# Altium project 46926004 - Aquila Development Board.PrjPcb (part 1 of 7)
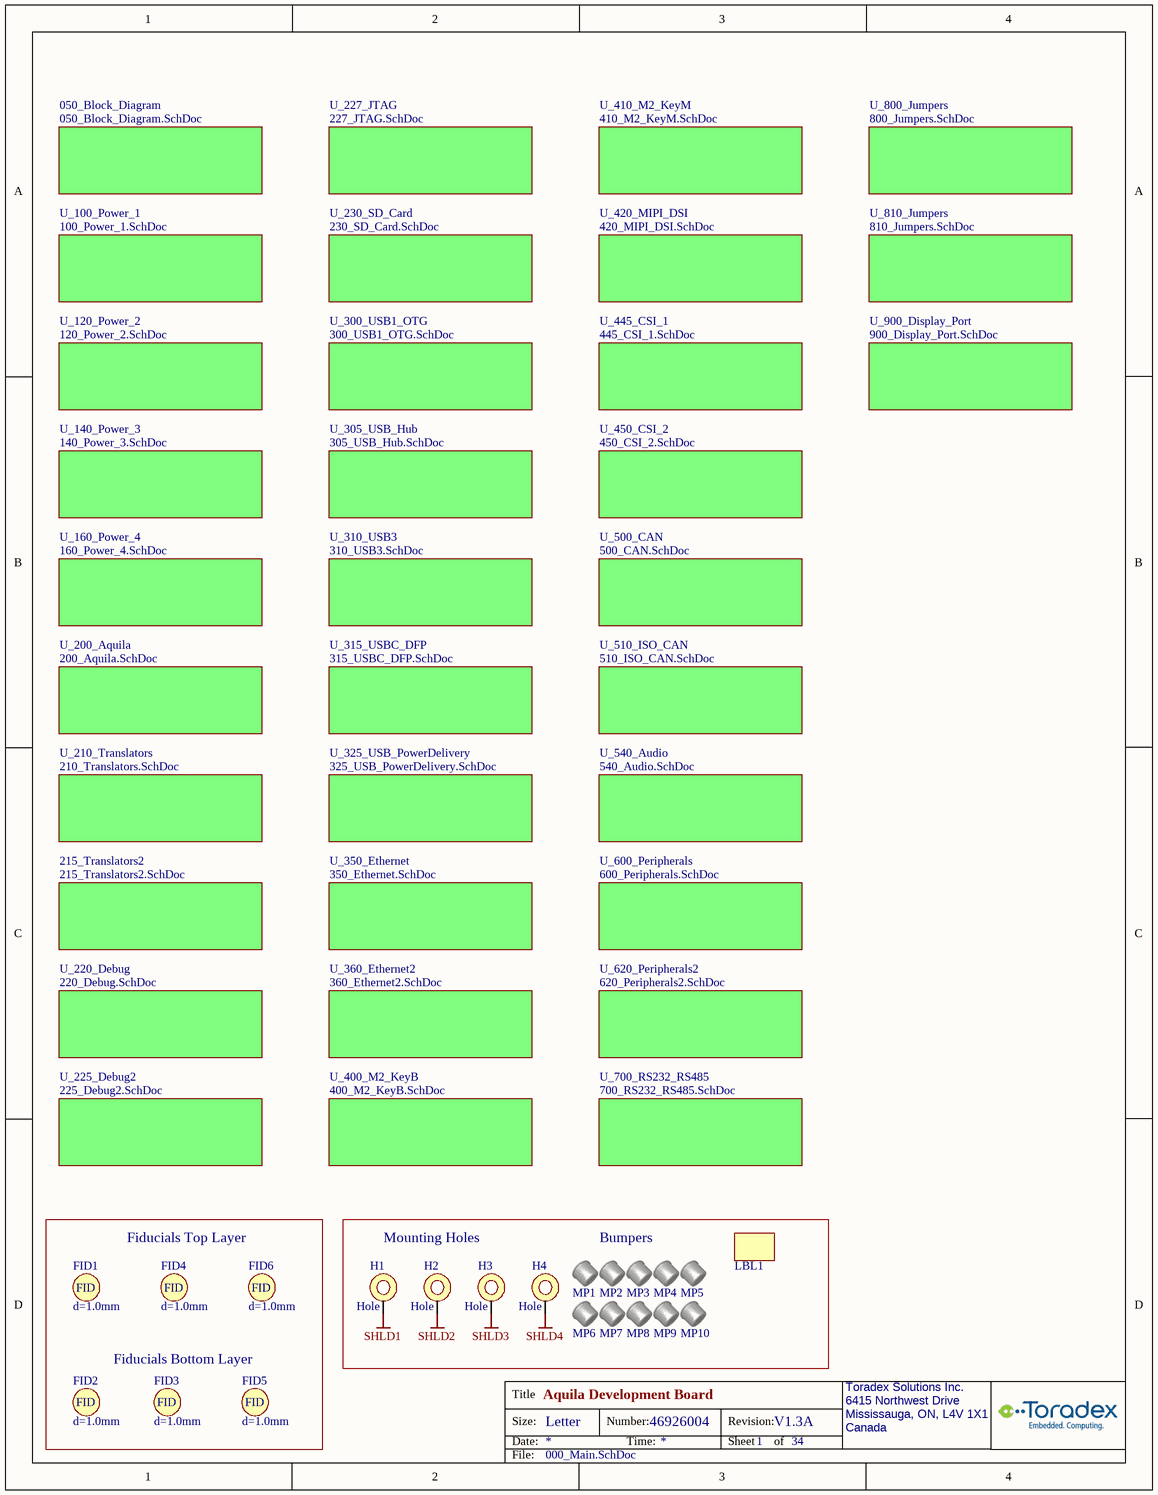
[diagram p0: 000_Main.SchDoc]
CompanyName: Toradex Solutions Inc.; DocumentNumber: 46926004; Revision: V1.3A; Title: Aquila Development Board
34 sheets, 1450 parts. Net scope: global (net labels, ports and power ports of the same name join across sheets).
Board file: 46926004.PcbDoc
Sheets:
  000_Main.SchDoc
    U_200_Aquila = 200_Aquila.SchDoc
    U_600_Peripherals = 600_Peripherals.SchDoc
    U_100_Power_1 = 100_Power_1.SchDoc
    U_210_Translators = 210_Translators.SchDoc
    U_220_Debug = 220_Debug.SchDoc
    U_300_USB1_OTG = 300_USB1_OTG.SchDoc
    U_310_USB3 = 310_USB3.SchDoc
    U_305_USB_Hub = 305_USB_Hub.SchDoc
    U_350_Ethernet = 350_Ethernet.SchDoc
    U_230_SD_Card = 230_SD_Card.SchDoc
    U_400_M2_KeyB = 400_M2_KeyB.SchDoc
    U_420_MIPI_DSI = 420_MIPI_DSI.SchDoc
    U_500_CAN = 500_CAN.SchDoc
    U_120_Power_2 = 120_Power_2.SchDoc
    U_140_Power_3 = 140_Power_3.SchDoc
    U_360_Ethernet2 = 360_Ethernet2.SchDoc
    U_410_M2_KeyM = 410_M2_KeyM.SchDoc
    U_540_Audio = 540_Audio.SchDoc
    U_620_Peripherals2 = 620_Peripherals2.SchDoc
    U_225_Debug2 = 225_Debug2.SchDoc
    U_227_JTAG = 227_JTAG.SchDoc
    215_Translators2 = 215_Translators2.SchDoc
    050_Block_Diagram = 050_Block_Diagram.SchDoc
    U_800_Jumpers = 800_Jumpers.SchDoc
    U_810_Jumpers = 810_Jumpers.SchDoc
    U_160_Power_4 = 160_Power_4.SchDoc
    U_510_ISO_CAN = 510_ISO_CAN.SchDoc
    U_325_USB_PowerDelivery = 325_USB_PowerDelivery.SchDoc
    U_700_RS232_RS485 = 700_RS232_RS485.SchDoc
    U_315_USBC_DFP = 315_USBC_DFP.SchDoc
    U_445_CSI_1 = 445_CSI_1.SchDoc
    U_450_CSI_2 = 450_CSI_2.SchDoc
    U_900_Display_Port = 900_Display_Port.SchDoc

## Sheet 000_Main.SchDoc: Aquila Development Board
size Letter portrait; Organization: Toradex Solutions Inc.; Address1: 6415 Northwest Drive; Address2: Mississauga, ON, L4V 1X1; Address3: Canada; SheetNumber: 1; SheetTotal: 34

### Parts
FID1  d=1.0mm  [FID_40X120_RND]  (no BOM)
FID2  d=1.0mm  [FID_40X120_RND]  (no BOM)
FID3  d=1.0mm  [FID_40X120_RND]  (no BOM)
FID4  d=1.0mm  [FID_40X120_RND]  (no BOM)
FID5  d=1.0mm  [FID_40X120_RND]  (no BOM)
FID6  d=1.0mm  [FID_40X120_RND]  (no BOM)
H1  Hole  [MTG_HOLE_0.125]  (no BOM)
H2  Hole  [MTG_HOLE_0.125]  (no BOM)
H3  Hole  [MTG_HOLE_0.125]  (no BOM)
H4  Hole  [MTG_HOLE_0.125]  (no BOM)
LBL1  SN Label 0.25x0.9 inch  [LABEL_0.25x0.9IN]  (value not drawn)  (no BOM)
MP1  SJ61A3  [3M-SJ61A3]  (value not drawn)
MP2  SJ61A3  [3M-SJ61A3]  (value not drawn)
MP3  SJ61A3  [3M-SJ61A3]  (value not drawn)
MP4  SJ61A3  [3M-SJ61A3]  (value not drawn)
MP5  SJ61A3  [3M-SJ61A3]  (value not drawn)
MP6  SJ61A3  [3M-SJ61A3]  (value not drawn)
MP7  SJ61A3  [3M-SJ61A3]  (value not drawn)
MP8  SJ61A3  [3M-SJ61A3]  (value not drawn)
MP9  SJ61A3  [3M-SJ61A3]  (value not drawn)
MP10  SJ61A3  [3M-SJ61A3]  (value not drawn)

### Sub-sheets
050_Block_Diagram = 050_Block_Diagram.SchDoc: no entries
215_Translators2 = 215_Translators2.SchDoc: no entries
U_100_Power_1 = 100_Power_1.SchDoc: no entries
U_120_Power_2 = 120_Power_2.SchDoc: no entries
U_140_Power_3 = 140_Power_3.SchDoc: no entries
U_160_Power_4 = 160_Power_4.SchDoc: no entries
U_200_Aquila = 200_Aquila.SchDoc: no entries
U_210_Translators = 210_Translators.SchDoc: no entries
U_220_Debug = 220_Debug.SchDoc: no entries
U_225_Debug2 = 225_Debug2.SchDoc: no entries
U_227_JTAG = 227_JTAG.SchDoc: no entries
U_230_SD_Card = 230_SD_Card.SchDoc: no entries
U_300_USB1_OTG = 300_USB1_OTG.SchDoc: no entries
U_305_USB_Hub = 305_USB_Hub.SchDoc: no entries
U_310_USB3 = 310_USB3.SchDoc: no entries
U_315_USBC_DFP = 315_USBC_DFP.SchDoc: no entries
U_325_USB_PowerDelivery = 325_USB_PowerDelivery.SchDoc: no entries
U_350_Ethernet = 350_Ethernet.SchDoc: no entries
U_360_Ethernet2 = 360_Ethernet2.SchDoc: no entries
U_400_M2_KeyB = 400_M2_KeyB.SchDoc: no entries
U_410_M2_KeyM = 410_M2_KeyM.SchDoc: no entries
U_420_MIPI_DSI = 420_MIPI_DSI.SchDoc: no entries
U_445_CSI_1 = 445_CSI_1.SchDoc: no entries
U_450_CSI_2 = 450_CSI_2.SchDoc: no entries
U_500_CAN = 500_CAN.SchDoc: no entries
U_510_ISO_CAN = 510_ISO_CAN.SchDoc: no entries
U_540_Audio = 540_Audio.SchDoc: no entries
U_600_Peripherals = 600_Peripherals.SchDoc: no entries
U_620_Peripherals2 = 620_Peripherals2.SchDoc: no entries
U_700_RS232_RS485 = 700_RS232_RS485.SchDoc: no entries
U_800_Jumpers = 800_Jumpers.SchDoc: no entries
U_810_Jumpers = 810_Jumpers.SchDoc: no entries
U_900_Display_Port = 900_Display_Port.SchDoc: no entries

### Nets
SHLD1: H1.0(MTG_HOLE)
SHLD2: H2.0(MTG_HOLE)
SHLD3: H3.0(MTG_HOLE)
SHLD4: H4.0(MTG_HOLE)

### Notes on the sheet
- Fiducials Top Layer
- Mounting Holes
- Bumpers
- Fiducials Bottom Layer

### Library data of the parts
FID1-FID6 = 0000-Fiducial-round: Fiducial round d=1.0mm
H1-H4 = 000-Hole-125mil
LBL1 = 000-Label-0.25x0.9IN: Label for Toradex serial number label 0.25x0.9 inch
MP1-MP10 = 1476-Bumper-10mmD-6mmH: (-40 to 85 DegC) Bumper Polyurethane, D: 9.5mm, H: 6.3mm, adhesive; Mfr: 3M; PN: 1476; Note: To be attached manually after SMT/TH assembly

## Sheet 200_Aquila.SchDoc: Aquila Development Board
size 566 x 398 mm; Organization: Toradex Solutions Inc.; Address1: 6415 Northwest Drive; Address2: Mississauga, ON, L4V 1X1; Address3: Canada; SheetNumber: 7; SheetTotal: 34
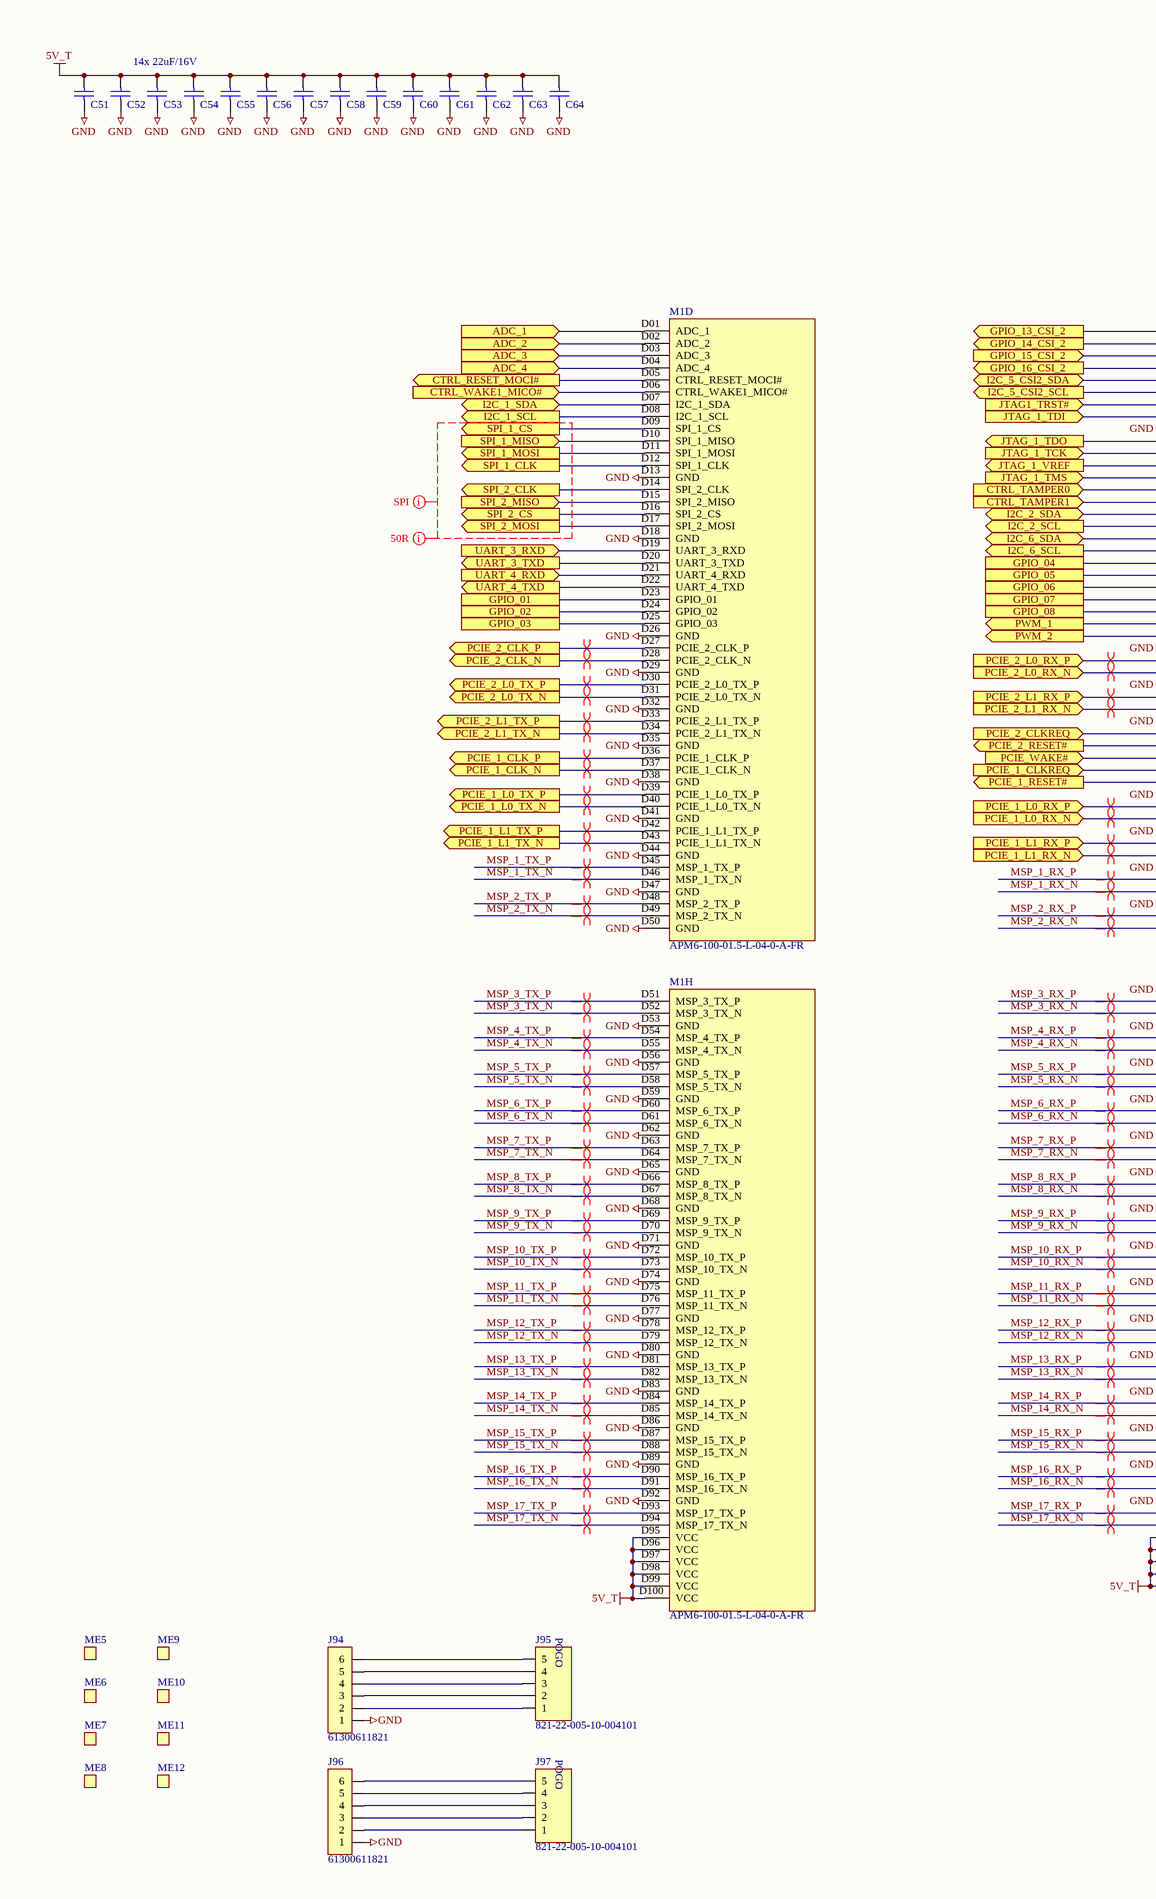
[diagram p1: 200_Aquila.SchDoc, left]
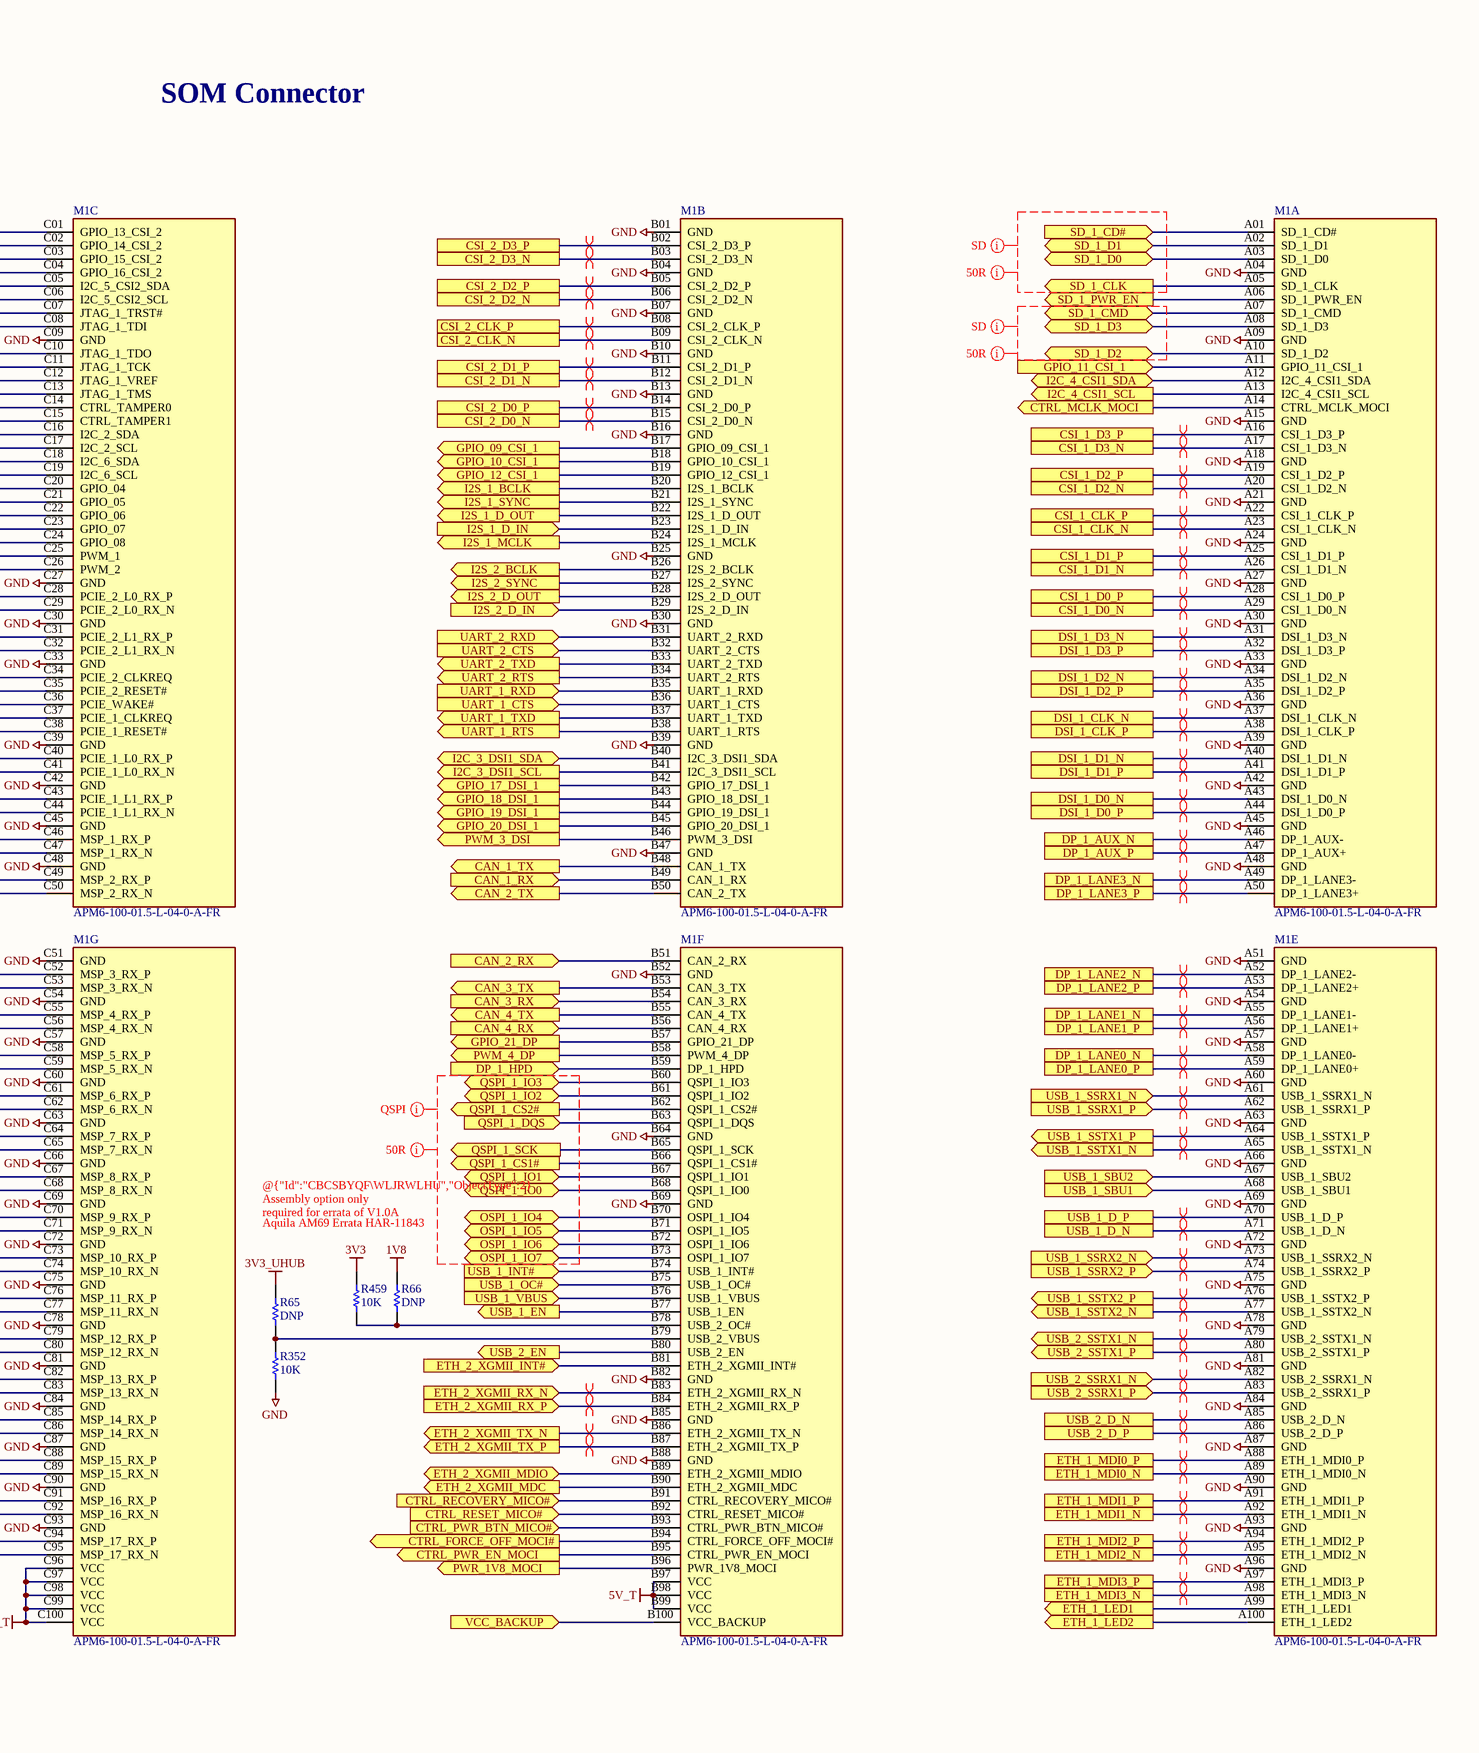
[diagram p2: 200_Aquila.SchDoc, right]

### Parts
C51  14x 22uF/16V  [C/0805]
C52  1314-Cap-0805-22uF/16V  [C/0805]  (value not drawn)
C53  1314-Cap-0805-22uF/16V  [C/0805]  (value not drawn)
C54  1314-Cap-0805-22uF/16V  [C/0805]  (value not drawn)
C55  1314-Cap-0805-22uF/16V  [C/0805]  (value not drawn)
C56  1314-Cap-0805-22uF/16V  [C/0805]  (value not drawn)
C57  1314-Cap-0805-22uF/16V  [C/0805]  (value not drawn)
C58  1314-Cap-0805-22uF/16V  [C/0805]  (value not drawn)
C59  1314-Cap-0805-22uF/16V  [C/0805]  (value not drawn)
C60  1314-Cap-0805-22uF/16V  [C/0805]  (value not drawn)
C61  1314-Cap-0805-22uF/16V  [C/0805]  (value not drawn)
C62  1314-Cap-0805-22uF/16V  [C/0805]  (value not drawn)
C63  1314-Cap-0805-22uF/16V  [C/0805]  (value not drawn)
C64  1314-Cap-0805-22uF/16V  [C/0805]  (value not drawn)
J94  61300611821  [WURTH_61300611821]
J95  821-22-005-10-004101  [POGO_821-22-005_MILL_MAX]
J96  61300611821  [WURTH_61300611821]
J97  821-22-005-10-004101  [POGO_821-22-005_MILL_MAX]
M1  APM6-100-01.5-L-04-0-A-FR  [SAMTEC_APM-100-01.5-L04-0-A]  (parts A,B,C,D,E,F,G,H of 8)
ME5  2405-Post-M3-5mm  [MTG_POST WURTH 9774050360R]  (value not drawn)
ME6  2405-Post-M3-5mm  [MTG_POST WURTH 9774050360R]  (value not drawn)
ME7  2405-Post-M3-5mm  [MTG_POST WURTH 9774050360R]  (value not drawn)
ME8  2405-Post-M3-5mm  [MTG_POST WURTH 9774050360R]  (value not drawn)
ME9  2405-Post-M3-5mm  [MTG_POST WURTH 9774050360R]  (value not drawn)
ME10  2405-Post-M3-5mm  [MTG_POST WURTH 9774050360R]  (value not drawn)
ME11  2405-Post-M3-5mm  [MTG_POST WURTH 9774050360R]  (value not drawn)
ME12  2405-Post-M3-5mm  [MTG_POST WURTH 9774050360R]  (value not drawn)
R65  value DNP  [R0402_RESC1005L]  (hidden comment: 0000-Res-0402-DNP)
R66  value DNP  [R0402_RESC1005L]  (hidden comment: 0000-Res-0402-DNP)  (no BOM)
R352  value 10K  [R0402_RESC1005L]  (hidden comment: 1572-Res-0402-10K)
R459  value 10K  [R0402_RESC1005L]  (hidden comment: 1572-Res-0402-10K)

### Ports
ADC_1 (in), ADC_2 (in), ADC_3 (in), ADC_4 (in), CAN_1_RX (in), CAN_1_TX (out), CAN_2_RX (in), CAN_2_TX (out), CAN_3_RX (in), CAN_3_TX (out), CAN_4_RX (in), CAN_4_TX (out), CSI_1_CLK_N, CSI_1_CLK_P, CSI_1_D0_N, CSI_1_D0_P, CSI_1_D1_N, CSI_1_D1_P, CSI_1_D2_N, CSI_1_D2_P, CSI_1_D3_N, CSI_1_D3_P, CSI_2_CLK_N, CSI_2_CLK_P, CSI_2_D0_N, CSI_2_D0_P, CSI_2_D1_N, CSI_2_D1_P, CSI_2_D2_N, CSI_2_D2_P, CSI_2_D3_N, CSI_2_D3_P, CTRL_FORCE_OFF_MOCI# (out), CTRL_MCLK_MOCI (out), CTRL_PWR_BTN_MICO# (in), CTRL_PWR_EN_MOCI (out), CTRL_RECOVERY_MICO# (in), CTRL_RESET_MICO# (in), CTRL_RESET_MOCI# (out), CTRL_TAMPER0 (in), CTRL_TAMPER1 (in), CTRL_WAKE1_MICO# (in), DP_1_AUX_N, DP_1_AUX_P, DP_1_HPD (in), DP_1_LANE0_N, DP_1_LANE0_P, DP_1_LANE1_N, DP_1_LANE1_P, DP_1_LANE2_N, DP_1_LANE2_P, DP_1_LANE3_N, DP_1_LANE3_P, DSI_1_CLK_N, DSI_1_CLK_P, DSI_1_D0_N, DSI_1_D0_P, DSI_1_D1_N, DSI_1_D1_P, DSI_1_D2_N, DSI_1_D2_P, DSI_1_D3_N, DSI_1_D3_P, ETH_1_LED1 (out), ETH_1_LED2 (out), ETH_1_MDI0_N, ETH_1_MDI0_P, ETH_1_MDI1_N, ETH_1_MDI1_P, ETH_1_MDI2_N, ETH_1_MDI2_P, ETH_1_MDI3_N, ETH_1_MDI3_P, ETH_2_XGMII_INT# (in), ETH_2_XGMII_MDC (out), ETH_2_XGMII_MDIO (bidir), ETH_2_XGMII_RX_N (in), ETH_2_XGMII_RX_P (in), ETH_2_XGMII_TX_N (out), ETH_2_XGMII_TX_P (out), GPIO_01, GPIO_02, GPIO_03, GPIO_04, GPIO_05, GPIO_06, GPIO_07, GPIO_08, GPIO_09_CSI_1 (out), GPIO_10_CSI_1 (out), GPIO_11_CSI_1 (in), GPIO_12_CSI_1 (out), GPIO_13_CSI_2 (out), GPIO_14_CSI_2 (out), GPIO_15_CSI_2 (in), GPIO_16_CSI_2 (out), GPIO_17_DSI_1 (out), GPIO_18_DSI_1 (out), GPIO_19_DSI_1 (out), GPIO_20_DSI_1 (out), GPIO_21_DP (out), I2C_1_SCL (out), I2C_1_SDA (bidir), I2C_2_SCL (out), I2C_2_SDA (bidir), I2C_3_DSI1_SCL (out), I2C_3_DSI1_SDA (bidir), I2C_4_CSI1_SCL (out), I2C_4_CSI1_SDA (bidir), I2C_5_CSI2_SCL (out), I2C_5_CSI2_SDA (bidir), I2C_6_SCL (out), I2C_6_SDA (bidir), I2S_1_BCLK (out), I2S_1_D_IN (in), I2S_1_D_OUT (out), I2S_1_MCLK (out), I2S_1_SYNC (out), I2S_2_BCLK (out), I2S_2_D_IN (in), I2S_2_D_OUT (out), I2S_2_SYNC (out), JTAG1_TRST# (in), JTAG_1_TCK (in), JTAG_1_TDI (in), JTAG_1_TDO (out), JTAG_1_TMS (in), JTAG_1_VREF (out), OSPI_1_IO4 (bidir), OSPI_1_IO5 (bidir), OSPI_1_IO6 (bidir), OSPI_1_IO7 (bidir), PCIE_1_CLK_N (out), PCIE_1_CLK_P (out), PCIE_1_CLKREQ (in), PCIE_1_L0_RX_N (in), PCIE_1_L0_RX_P (in), PCIE_1_L0_TX_N (out), PCIE_1_L0_TX_P (out), PCIE_1_L1_RX_N (in), PCIE_1_L1_RX_P (in), PCIE_1_L1_TX_N (out), PCIE_1_L1_TX_P (out), PCIE_1_RESET# (out), PCIE_2_CLK_N (out), PCIE_2_CLK_P (out), PCIE_2_CLKREQ (in), PCIE_2_L0_RX_N (in), PCIE_2_L0_RX_P (in), PCIE_2_L0_TX_N (out), PCIE_2_L0_TX_P (out), PCIE_2_L1_RX_N (in), PCIE_2_L1_RX_P (in), PCIE_2_L1_TX_N (out), PCIE_2_L1_TX_P (out), PCIE_2_RESET# (out), PCIE_WAKE# (in), PWM_1 (out), PWM_2 (out), PWM_3_DSI (out), PWM_4_DP (out), PWR_1V8_MOCI (out), QSPI_1_CS1# (out), QSPI_1_CS2# (out), QSPI_1_DQS (in), QSPI_1_IO0 (bidir), QSPI_1_IO1 (bidir), QSPI_1_IO2 (bidir), QSPI_1_IO3 (bidir), QSPI_1_SCK (out), SD_1_CD# (in), SD_1_CLK (out), SD_1_CMD (bidir), SD_1_D0 (bidir), SD_1_D1 (bidir), SD_1_D2 (bidir), SD_1_D3 (bidir), SD_1_PWR_EN (out), SPI_1_CLK (out), SPI_1_CS (out), SPI_1_MISO (in), SPI_1_MOSI (out), SPI_2_CLK (out), SPI_2_CS (out), SPI_2_MISO (in), SPI_2_MOSI (out), UART_1_CTS (in), UART_1_RTS (out), UART_1_RXD (in), UART_1_TXD (out), UART_2_CTS (in), UART_2_RTS (out), UART_2_RXD (in), UART_2_TXD (out), UART_3_RXD (in), UART_3_TXD (out), UART_4_RXD (in), UART_4_TXD (out), USB_1_D_N, USB_1_D_P, USB_1_EN (out), USB_1_INT# (in), USB_1_OC# (in), USB_1_SBU1 (in), USB_1_SBU2 (in), USB_1_SSRX1_N (in), USB_1_SSRX1_P (in), USB_1_SSRX2_N (in), USB_1_SSRX2_P (in), USB_1_SSTX1_N (out), USB_1_SSTX1_P (out), USB_1_SSTX2_N (out), USB_1_SSTX2_P (out), USB_1_VBUS (in), USB_2_D_N, USB_2_D_P, USB_2_EN (out), USB_2_SSRX1_N (in), USB_2_SSRX1_P (in), USB_2_SSTX1_N (out), USB_2_SSTX1_P (out), VCC_BACKUP (in)

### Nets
1V8: R66.1
3V3: R459.1
3V3_UHUB: R65.1
5V_T: C51.2 C52.2 C53.2 C54.2 C55.2 C56.2 C57.2 C58.2 C59.2 C60.2 C61.2 C62.2 C63.2 C64.2 M1.B97(VCC) M1.B98(VCC) M1.B99(VCC) M1.C96(VCC) M1.C97(VCC) M1.C98(VCC) M1.C99(VCC) M1.C100(VCC) M1.D95(VCC) M1.D96(VCC) M1.D97(VCC) M1.D98(VCC) M1.D99(VCC) M1.D100(VCC)
GND: C51.1 C52.1 C53.1 C54.1 C55.1 C56.1 C57.1 C58.1 C59.1 C60.1 C61.1 C62.1 C63.1 C64.1 J94.1 J96.1 M1.A04(GND) M1.A09(GND) M1.A15(GND) M1.A18(GND) M1.A21(GND) M1.A24(GND) M1.A27(GND) M1.A30(GND) M1.A33(GND) M1.A36(GND) M1.A39(GND) M1.A42(GND) M1.A45(GND) M1.A48(GND) M1.A51(GND) M1.A54(GND) M1.A57(GND) M1.A60(GND) M1.A63(GND) M1.A66(GND) M1.A69(GND) M1.A72(GND) M1.A75(GND) M1.A78(GND) M1.A81(GND) M1.A84(GND) M1.A87(GND) M1.A90(GND) M1.A93(GND) M1.A96(GND) M1.B01(GND) M1.B04(GND) M1.B07(GND) M1.B10(GND) M1.B13(GND) M1.B16(GND) M1.B25(GND) M1.B30(GND) M1.B39(GND) M1.B47(GND) M1.B52(GND) M1.B64(GND) M1.B69(GND) M1.B82(GND) M1.B85(GND) M1.B88(GND) M1.C09(GND) M1.C27(GND) M1.C30(GND) M1.C33(GND) M1.C39(GND) M1.C42(GND) M1.C45(GND) M1.C48(GND) M1.C51(GND) M1.C54(GND) M1.C57(GND) M1.C60(GND) M1.C63(GND) M1.C66(GND) M1.C69(GND) M1.C72(GND) M1.C75(GND) M1.C78(GND) M1.C81(GND) M1.C84(GND) M1.C87(GND) M1.C90(GND) M1.C93(GND) M1.D13(GND) M1.D18(GND) M1.D26(GND) M1.D29(GND) M1.D32(GND) M1.D35(GND) M1.D38(GND) M1.D41(GND) M1.D44(GND) M1.D47(GND) M1.D50(GND) M1.D53(GND) M1.D56(GND) M1.D59(GND) M1.D62(GND) M1.D65(GND) M1.D68(GND) M1.D71(GND) M1.D74(GND) M1.D77(GND) M1.D80(GND) M1.D83(GND) M1.D86(GND) M1.D89(GND) M1.D92(GND) R352.2
ADC_1: M1.D01(ADC_1) ; port ADC_1
ADC_2: M1.D02(ADC_2) ; port ADC_2
ADC_3: M1.D03(ADC_3) ; port ADC_3
ADC_4: M1.D04(ADC_4) ; port ADC_4
CAN_1_RX: M1.B49(CAN_1_RX) ; port CAN_1_RX
CAN_1_TX: M1.B48(CAN_1_TX) ; port CAN_1_TX
CAN_2_RX: M1.B51(CAN_2_RX) ; port CAN_2_RX
CAN_2_TX: M1.B50(CAN_2_TX) ; port CAN_2_TX
CAN_3_RX: M1.B54(CAN_3_RX) ; port CAN_3_RX
CAN_3_TX: M1.B53(CAN_3_TX) ; port CAN_3_TX
CAN_4_RX: M1.B56(CAN_4_RX) ; port CAN_4_RX
CAN_4_TX: M1.B55(CAN_4_TX) ; port CAN_4_TX
CSI_1_CLK_N: M1.A23(CSI_1_CLK_N) ; port CSI_1_CLK_N
CSI_1_CLK_P: M1.A22(CSI_1_CLK_P) ; port CSI_1_CLK_P
CSI_1_D0_N: M1.A29(CSI_1_D0_N) ; port CSI_1_D0_N
CSI_1_D0_P: M1.A28(CSI_1_D0_P) ; port CSI_1_D0_P
CSI_1_D1_N: M1.A26(CSI_1_D1_N) ; port CSI_1_D1_N
CSI_1_D1_P: M1.A25(CSI_1_D1_P) ; port CSI_1_D1_P
CSI_1_D2_N: M1.A20(CSI_1_D2_N) ; port CSI_1_D2_N
CSI_1_D2_P: M1.A19(CSI_1_D2_P) ; port CSI_1_D2_P
CSI_1_D3_N: M1.A17(CSI_1_D3_N) ; port CSI_1_D3_N
CSI_1_D3_P: M1.A16(CSI_1_D3_P) ; port CSI_1_D3_P
CSI_2_CLK_N: M1.B09(CSI_2_CLK_N) ; port CSI_2_CLK_N
CSI_2_CLK_P: M1.B08(CSI_2_CLK_P) ; port CSI_2_CLK_P
CSI_2_D0_N: M1.B15(CSI_2_D0_N) ; port CSI_2_D0_N
CSI_2_D0_P: M1.B14(CSI_2_D0_P) ; port CSI_2_D0_P
CSI_2_D1_N: M1.B12(CSI_2_D1_N) ; port CSI_2_D1_N
CSI_2_D1_P: M1.B11(CSI_2_D1_P) ; port CSI_2_D1_P
CSI_2_D2_N: M1.B06(CSI_2_D2_N) ; port CSI_2_D2_N
CSI_2_D2_P: M1.B05(CSI_2_D2_P) ; port CSI_2_D2_P
CSI_2_D3_N: M1.B03(CSI_2_D3_N) ; port CSI_2_D3_N
CSI_2_D3_P: M1.B02(CSI_2_D3_P) ; port CSI_2_D3_P
CTRL_FORCE_OFF_MOCI#: M1.B94(CTRL_FORCE_OFF_MOCI#) ; port CTRL_FORCE_OFF_MOCI#
CTRL_MCLK_MOCI: M1.A14(CTRL_MCLK_MOCI) ; port CTRL_MCLK_MOCI
CTRL_PWR_BTN_MICO#: M1.B93(CTRL_PWR_BTN_MICO#) ; port CTRL_PWR_BTN_MICO#
CTRL_PWR_EN_MOCI: M1.B95(CTRL_PWR_EN_MOCI) ; port CTRL_PWR_EN_MOCI
CTRL_RECOVERY_MICO#: M1.B91(CTRL_RECOVERY_MICO#) ; port CTRL_RECOVERY_MICO#
CTRL_RESET_MICO#: M1.B92(CTRL_RESET_MICO#) ; port CTRL_RESET_MICO#
CTRL_RESET_MOCI#: M1.D05(CTRL_RESET_MOCI#) ; port CTRL_RESET_MOCI#
CTRL_TAMPER0: M1.C14(CTRL_TAMPER0) ; port CTRL_TAMPER0
CTRL_TAMPER1: M1.C15(CTRL_TAMPER1) ; port CTRL_TAMPER1
CTRL_WAKE1_MICO#: M1.D06(CTRL_WAKE1_MICO#) ; port CTRL_WAKE1_MICO#
DP_1_AUX_N: M1.A46(DP_1_AUX-) ; port DP_1_AUX_N
DP_1_AUX_P: M1.A47(DP_1_AUX+) ; port DP_1_AUX_P
DP_1_HPD: M1.B59(DP_1_HPD) ; port DP_1_HPD
DP_1_LANE0_N: M1.A58(DP_1_LANE0-) ; port DP_1_LANE0_N
DP_1_LANE0_P: M1.A59(DP_1_LANE0+) ; port DP_1_LANE0_P
DP_1_LANE1_N: M1.A55(DP_1_LANE1-) ; port DP_1_LANE1_N
DP_1_LANE1_P: M1.A56(DP_1_LANE1+) ; port DP_1_LANE1_P
DP_1_LANE2_N: M1.A52(DP_1_LANE2-) ; port DP_1_LANE2_N
DP_1_LANE2_P: M1.A53(DP_1_LANE2+) ; port DP_1_LANE2_P
DP_1_LANE3_N: M1.A49(DP_1_LANE3-) ; port DP_1_LANE3_N
DP_1_LANE3_P: M1.A50(DP_1_LANE3+) ; port DP_1_LANE3_P
DSI_1_CLK_N: M1.A37(DSI_1_CLK_N) ; port DSI_1_CLK_N
DSI_1_CLK_P: M1.A38(DSI_1_CLK_P) ; port DSI_1_CLK_P
DSI_1_D0_N: M1.A43(DSI_1_D0_N) ; port DSI_1_D0_N
DSI_1_D0_P: M1.A44(DSI_1_D0_P) ; port DSI_1_D0_P
DSI_1_D1_N: M1.A40(DSI_1_D1_N) ; port DSI_1_D1_N
DSI_1_D1_P: M1.A41(DSI_1_D1_P) ; port DSI_1_D1_P
DSI_1_D2_N: M1.A34(DSI_1_D2_N) ; port DSI_1_D2_N
DSI_1_D2_P: M1.A35(DSI_1_D2_P) ; port DSI_1_D2_P
DSI_1_D3_N: M1.A31(DSI_1_D3_N) ; port DSI_1_D3_N
DSI_1_D3_P: M1.A32(DSI_1_D3_P) ; port DSI_1_D3_P
ETH_1_LED1: M1.A99(ETH_1_LED1) ; port ETH_1_LED1
ETH_1_LED2: M1.A100(ETH_1_LED2) ; port ETH_1_LED2
ETH_1_MDI0_N: M1.A89(ETH_1_MDI0_N) ; port ETH_1_MDI0_N
ETH_1_MDI0_P: M1.A88(ETH_1_MDI0_P) ; port ETH_1_MDI0_P
ETH_1_MDI1_N: M1.A92(ETH_1_MDI1_N) ; port ETH_1_MDI1_N
ETH_1_MDI1_P: M1.A91(ETH_1_MDI1_P) ; port ETH_1_MDI1_P
ETH_1_MDI2_N: M1.A95(ETH_1_MDI2_N) ; port ETH_1_MDI2_N
ETH_1_MDI2_P: M1.A94(ETH_1_MDI2_P) ; port ETH_1_MDI2_P
ETH_1_MDI3_N: M1.A98(ETH_1_MDI3_N) ; port ETH_1_MDI3_N
ETH_1_MDI3_P: M1.A97(ETH_1_MDI3_P) ; port ETH_1_MDI3_P
ETH_2_XGMII_INT#: M1.B81(ETH_2_XGMII_INT#) ; port ETH_2_XGMII_INT#
ETH_2_XGMII_MDC: M1.B90(ETH_2_XGMII_MDC) ; port ETH_2_XGMII_MDC
ETH_2_XGMII_MDIO: M1.B89(ETH_2_XGMII_MDIO) ; port ETH_2_XGMII_MDIO
ETH_2_XGMII_RX_N: M1.B83(ETH_2_XGMII_RX_N) ; port ETH_2_XGMII_RX_N
ETH_2_XGMII_RX_P: M1.B84(ETH_2_XGMII_RX_P) ; port ETH_2_XGMII_RX_P
ETH_2_XGMII_TX_N: M1.B86(ETH_2_XGMII_TX_N) ; port ETH_2_XGMII_TX_N
ETH_2_XGMII_TX_P: M1.B87(ETH_2_XGMII_TX_P) ; port ETH_2_XGMII_TX_P
GPIO_01: M1.D23(GPIO_01) ; port GPIO_01
GPIO_02: M1.D24(GPIO_02) ; port GPIO_02
GPIO_03: M1.D25(GPIO_03) ; port GPIO_03
GPIO_04: M1.C20(GPIO_04) ; port GPIO_04
GPIO_05: M1.C21(GPIO_05) ; port GPIO_05
GPIO_06: M1.C22(GPIO_06) ; port GPIO_06
GPIO_07: M1.C23(GPIO_07) ; port GPIO_07
GPIO_08: M1.C24(GPIO_08) ; port GPIO_08
GPIO_09_CSI_1: M1.B17(GPIO_09_CSI_1) ; port GPIO_09_CSI_1
GPIO_10_CSI_1: M1.B18(GPIO_10_CSI_1) ; port GPIO_10_CSI_1
GPIO_11_CSI_1: M1.A11(GPIO_11_CSI_1) ; port GPIO_11_CSI_1
GPIO_12_CSI_1: M1.B19(GPIO_12_CSI_1) ; port GPIO_12_CSI_1
GPIO_13_CSI_2: M1.C01(GPIO_13_CSI_2) ; port GPIO_13_CSI_2
GPIO_14_CSI_2: M1.C02(GPIO_14_CSI_2) ; port GPIO_14_CSI_2
GPIO_15_CSI_2: M1.C03(GPIO_15_CSI_2) ; port GPIO_15_CSI_2
GPIO_16_CSI_2: M1.C04(GPIO_16_CSI_2) ; port GPIO_16_CSI_2
GPIO_17_DSI_1: M1.B42(GPIO_17_DSI_1) ; port GPIO_17_DSI_1
GPIO_18_DSI_1: M1.B43(GPIO_18_DSI_1) ; port GPIO_18_DSI_1
GPIO_19_DSI_1: M1.B44(GPIO_19_DSI_1) ; port GPIO_19_DSI_1
GPIO_20_DSI_1: M1.B45(GPIO_20_DSI_1) ; port GPIO_20_DSI_1
GPIO_21_DP: M1.B57(GPIO_21_DP) ; port GPIO_21_DP
I2C_1_SCL: M1.D08(I2C_1_SCL) ; port I2C_1_SCL
I2C_1_SDA: M1.D07(I2C_1_SDA) ; port I2C_1_SDA
I2C_2_SCL: M1.C17(I2C_2_SCL) ; port I2C_2_SCL
I2C_2_SDA: M1.C16(I2C_2_SDA) ; port I2C_2_SDA
I2C_3_DSI1_SCL: M1.B41(I2C_3_DSI1_SCL) ; port I2C_3_DSI1_SCL
I2C_3_DSI1_SDA: M1.B40(I2C_3_DSI1_SDA) ; port I2C_3_DSI1_SDA
I2C_4_CSI1_SCL: M1.A13(I2C_4_CSI1_SCL) ; port I2C_4_CSI1_SCL
I2C_4_CSI1_SDA: M1.A12(I2C_4_CSI1_SDA) ; port I2C_4_CSI1_SDA
I2C_5_CSI2_SCL: M1.C06(I2C_5_CSI2_SCL) ; port I2C_5_CSI2_SCL
I2C_5_CSI2_SDA: M1.C05(I2C_5_CSI2_SDA) ; port I2C_5_CSI2_SDA
I2C_6_SCL: M1.C19(I2C_6_SCL) ; port I2C_6_SCL
I2C_6_SDA: M1.C18(I2C_6_SDA) ; port I2C_6_SDA
I2S_1_BCLK: M1.B20(I2S_1_BCLK) ; port I2S_1_BCLK
I2S_1_D_IN: M1.B23(I2S_1_D_IN) ; port I2S_1_D_IN
I2S_1_D_OUT: M1.B22(I2S_1_D_OUT) ; port I2S_1_D_OUT
I2S_1_MCLK: M1.B24(I2S_1_MCLK) ; port I2S_1_MCLK
I2S_1_SYNC: M1.B21(I2S_1_SYNC) ; port I2S_1_SYNC
I2S_2_BCLK: M1.B26(I2S_2_BCLK) ; port I2S_2_BCLK
I2S_2_D_IN: M1.B29(I2S_2_D_IN) ; port I2S_2_D_IN
I2S_2_D_OUT: M1.B28(I2S_2_D_OUT) ; port I2S_2_D_OUT
I2S_2_SYNC: M1.B27(I2S_2_SYNC) ; port I2S_2_SYNC
JTAG1_TRST#: M1.C07(JTAG_1_TRST#) ; port JTAG1_TRST#
JTAG_1_TCK: M1.C11(JTAG_1_TCK) ; port JTAG_1_TCK
JTAG_1_TDI: M1.C08(JTAG_1_TDI) ; port JTAG_1_TDI
JTAG_1_TDO: M1.C10(JTAG_1_TDO) ; port JTAG_1_TDO
JTAG_1_TMS: M1.C13(JTAG_1_TMS) ; port JTAG_1_TMS
JTAG_1_VREF: M1.C12(JTAG_1_VREF) ; port JTAG_1_VREF
MSP_1_RX_N: M1.C47(MSP_1_RX_N)
MSP_1_RX_P: M1.C46(MSP_1_RX_P)
MSP_1_TX_N: M1.D46(MSP_1_TX_N)
MSP_1_TX_P: M1.D45(MSP_1_TX_P)
MSP_2_RX_N: M1.C50(MSP_2_RX_N)
MSP_2_RX_P: M1.C49(MSP_2_RX_P)
MSP_2_TX_N: M1.D49(MSP_2_TX_N)
MSP_2_TX_P: M1.D48(MSP_2_TX_P)
MSP_3_RX_N: M1.C53(MSP_3_RX_N)
MSP_3_RX_P: M1.C52(MSP_3_RX_P)
MSP_3_TX_N: M1.D52(MSP_3_TX_N)
MSP_3_TX_P: M1.D51(MSP_3_TX_P)
MSP_4_RX_N: M1.C56(MSP_4_RX_N)
MSP_4_RX_P: M1.C55(MSP_4_RX_P)
MSP_4_TX_N: M1.D55(MSP_4_TX_N)
MSP_4_TX_P: M1.D54(MSP_4_TX_P)
MSP_5_RX_N: M1.C59(MSP_5_RX_N)
MSP_5_RX_P: M1.C58(MSP_5_RX_P)
MSP_5_TX_N: M1.D58(MSP_5_TX_N)
MSP_5_TX_P: M1.D57(MSP_5_TX_P)
MSP_6_RX_N: M1.C62(MSP_6_RX_N)
MSP_6_RX_P: M1.C61(MSP_6_RX_P)
MSP_6_TX_N: M1.D61(MSP_6_TX_N)
MSP_6_TX_P: M1.D60(MSP_6_TX_P)
MSP_7_RX_N: M1.C65(MSP_7_RX_N)
MSP_7_RX_P: M1.C64(MSP_7_RX_P)
MSP_7_TX_N: M1.D64(MSP_7_TX_N)
MSP_7_TX_P: M1.D63(MSP_7_TX_P)
MSP_8_RX_N: M1.C68(MSP_8_RX_N)
MSP_8_RX_P: M1.C67(MSP_8_RX_P)
MSP_8_TX_N: M1.D67(MSP_8_TX_N)
MSP_8_TX_P: M1.D66(MSP_8_TX_P)
MSP_9_RX_N: M1.C71(MSP_9_RX_N)
MSP_9_RX_P: M1.C70(MSP_9_RX_P)
MSP_9_TX_N: M1.D70(MSP_9_TX_N)
MSP_9_TX_P: M1.D69(MSP_9_TX_P)
MSP_10_RX_N: M1.C74(MSP_10_RX_N)
MSP_10_RX_P: M1.C73(MSP_10_RX_P)
MSP_10_TX_N: M1.D73(MSP_10_TX_N)
MSP_10_TX_P: M1.D72(MSP_10_TX_P)
MSP_11_RX_N: M1.C77(MSP_11_RX_N)
MSP_11_RX_P: M1.C76(MSP_11_RX_P)
MSP_11_TX_N: M1.D76(MSP_11_TX_N)
MSP_11_TX_P: M1.D75(MSP_11_TX_P)
MSP_12_RX_N: M1.C80(MSP_12_RX_N)
MSP_12_RX_P: M1.C79(MSP_12_RX_P)
MSP_12_TX_N: M1.D79(MSP_12_TX_N)
MSP_12_TX_P: M1.D78(MSP_12_TX_P)
MSP_13_RX_N: M1.C83(MSP_13_RX_N)
MSP_13_RX_P: M1.C82(MSP_13_RX_P)
MSP_13_TX_N: M1.D82(MSP_13_TX_N)
MSP_13_TX_P: M1.D81(MSP_13_TX_P)
MSP_14_RX_N: M1.C86(MSP_14_RX_N)
MSP_14_RX_P: M1.C85(MSP_14_RX_P)
MSP_14_TX_N: M1.D85(MSP_14_TX_N)
MSP_14_TX_P: M1.D84(MSP_14_TX_P)
MSP_15_RX_N: M1.C89(MSP_15_RX_N)
MSP_15_RX_P: M1.C88(MSP_15_RX_P)
MSP_15_TX_N: M1.D88(MSP_15_TX_N)
MSP_15_TX_P: M1.D87(MSP_15_TX_P)
MSP_16_RX_N: M1.C92(MSP_16_RX_N)
MSP_16_RX_P: M1.C91(MSP_16_RX_P)
MSP_16_TX_N: M1.D91(MSP_16_TX_N)
MSP_16_TX_P: M1.D90(MSP_16_TX_P)
MSP_17_RX_N: M1.C95(MSP_17_RX_N)
MSP_17_RX_P: M1.C94(MSP_17_RX_P)
MSP_17_TX_N: M1.D94(MSP_17_TX_N)
MSP_17_TX_P: M1.D93(MSP_17_TX_P)
OSPI_1_IO4: M1.B70(OSPI_1_IO4) ; port OSPI_1_IO4
OSPI_1_IO5: M1.B71(OSPI_1_IO5) ; port OSPI_1_IO5
OSPI_1_IO6: M1.B72(OSPI_1_IO6) ; port OSPI_1_IO6
OSPI_1_IO7: M1.B73(OSPI_1_IO7) ; port OSPI_1_IO7
PCIE_1_CLK_N: M1.D37(PCIE_1_CLK_N) ; port PCIE_1_CLK_N
PCIE_1_CLK_P: M1.D36(PCIE_1_CLK_P) ; port PCIE_1_CLK_P
PCIE_1_CLKREQ: M1.C37(PCIE_1_CLKREQ) ; port PCIE_1_CLKREQ
PCIE_1_L0_RX_N: M1.C41(PCIE_1_L0_RX_N) ; port PCIE_1_L0_RX_N
PCIE_1_L0_RX_P: M1.C40(PCIE_1_L0_RX_P) ; port PCIE_1_L0_RX_P
PCIE_1_L0_TX_N: M1.D40(PCIE_1_L0_TX_N) ; port PCIE_1_L0_TX_N
PCIE_1_L0_TX_P: M1.D39(PCIE_1_L0_TX_P) ; port PCIE_1_L0_TX_P
PCIE_1_L1_RX_N: M1.C44(PCIE_1_L1_RX_N) ; port PCIE_1_L1_RX_N
PCIE_1_L1_RX_P: M1.C43(PCIE_1_L1_RX_P) ; port PCIE_1_L1_RX_P
PCIE_1_L1_TX_N: M1.D43(PCIE_1_L1_TX_N) ; port PCIE_1_L1_TX_N
PCIE_1_L1_TX_P: M1.D42(PCIE_1_L1_TX_P) ; port PCIE_1_L1_TX_P
PCIE_1_RESET#: M1.C38(PCIE_1_RESET#) ; port PCIE_1_RESET#
PCIE_2_CLK_N: M1.D28(PCIE_2_CLK_N) ; port PCIE_2_CLK_N
PCIE_2_CLK_P: M1.D27(PCIE_2_CLK_P) ; port PCIE_2_CLK_P
PCIE_2_CLKREQ: M1.C34(PCIE_2_CLKREQ) ; port PCIE_2_CLKREQ
PCIE_2_L0_RX_N: M1.C29(PCIE_2_L0_RX_N) ; port PCIE_2_L0_RX_N
PCIE_2_L0_RX_P: M1.C28(PCIE_2_L0_RX_P) ; port PCIE_2_L0_RX_P
PCIE_2_L0_TX_N: M1.D31(PCIE_2_L0_TX_N) ; port PCIE_2_L0_TX_N
PCIE_2_L0_TX_P: M1.D30(PCIE_2_L0_TX_P) ; port PCIE_2_L0_TX_P
PCIE_2_L1_RX_N: M1.C32(PCIE_2_L1_RX_N) ; port PCIE_2_L1_RX_N
PCIE_2_L1_RX_P: M1.C31(PCIE_2_L1_RX_P) ; port PCIE_2_L1_RX_P
PCIE_2_L1_TX_N: M1.D34(PCIE_2_L1_TX_N) ; port PCIE_2_L1_TX_N
PCIE_2_L1_TX_P: M1.D33(PCIE_2_L1_TX_P) ; port PCIE_2_L1_TX_P
PCIE_2_RESET#: M1.C35(PCIE_2_RESET#) ; port PCIE_2_RESET#
PCIE_WAKE#: M1.C36(PCIE_WAKE#) ; port PCIE_WAKE#
PWM_1: M1.C25(PWM_1) ; port PWM_1
PWM_2: M1.C26(PWM_2) ; port PWM_2
PWM_3_DSI: M1.B46(PWM_3_DSI) ; port PWM_3_DSI
PWM_4_DP: M1.B58(PWM_4_DP) ; port PWM_4_DP
PWR_1V8_MOCI: M1.B96(PWR_1V8_MOCI) ; port PWR_1V8_MOCI
QSPI_1_CS1#: M1.B66(QSPI_1_CS1#) ; port QSPI_1_CS1#
QSPI_1_CS2#: M1.B62(QSPI_1_CS2#) ; port QSPI_1_CS2#
QSPI_1_DQS: M1.B63(QSPI_1_DQS) ; port QSPI_1_DQS
QSPI_1_IO0: M1.B68(QSPI_1_IO0) ; port QSPI_1_IO0
QSPI_1_IO1: M1.B67(QSPI_1_IO1) ; port QSPI_1_IO1
QSPI_1_IO2: M1.B61(QSPI_1_IO2) ; port QSPI_1_IO2
QSPI_1_IO3: M1.B60(QSPI_1_IO3) ; port QSPI_1_IO3
QSPI_1_SCK: M1.B65(QSPI_1_SCK) ; port QSPI_1_SCK
SD_1_CD#: M1.A01(SD_1_CD#) ; port SD_1_CD#
SD_1_CLK: M1.A05(SD_1_CLK) ; port SD_1_CLK
SD_1_CMD: M1.A07(SD_1_CMD) ; port SD_1_CMD
SD_1_D0: M1.A03(SD_1_D0) ; port SD_1_D0
SD_1_D1: M1.A02(SD_1_D1) ; port SD_1_D1
SD_1_D2: M1.A10(SD_1_D2) ; port SD_1_D2
SD_1_D3: M1.A08(SD_1_D3) ; port SD_1_D3
SD_1_PWR_EN: M1.A06(SD_1_PWR_EN) ; port SD_1_PWR_EN
SPI_1_CLK: M1.D12(SPI_1_CLK) ; port SPI_1_CLK
SPI_1_CS: M1.D09(SPI_1_CS) ; port SPI_1_CS
SPI_1_MISO: M1.D10(SPI_1_MISO) ; port SPI_1_MISO
SPI_1_MOSI: M1.D11(SPI_1_MOSI) ; port SPI_1_MOSI
SPI_2_CLK: M1.D14(SPI_2_CLK) ; port SPI_2_CLK
SPI_2_CS: M1.D16(SPI_2_CS) ; port SPI_2_CS
SPI_2_MISO: M1.D15(SPI_2_MISO) ; port SPI_2_MISO
SPI_2_MOSI: M1.D17(SPI_2_MOSI) ; port SPI_2_MOSI
UART_1_CTS: M1.B36(UART_1_CTS) ; port UART_1_CTS
UART_1_RTS: M1.B38(UART_1_RTS) ; port UART_1_RTS
UART_1_RXD: M1.B35(UART_1_RXD) ; port UART_1_RXD
UART_1_TXD: M1.B37(UART_1_TXD) ; port UART_1_TXD
UART_2_CTS: M1.B32(UART_2_CTS) ; port UART_2_CTS
UART_2_RTS: M1.B34(UART_2_RTS) ; port UART_2_RTS
UART_2_RXD: M1.B31(UART_2_RXD) ; port UART_2_RXD
UART_2_TXD: M1.B33(UART_2_TXD) ; port UART_2_TXD
UART_3_RXD: M1.D19(UART_3_RXD) ; port UART_3_RXD
UART_3_TXD: M1.D20(UART_3_TXD) ; port UART_3_TXD
UART_4_RXD: M1.D21(UART_4_RXD) ; port UART_4_RXD
UART_4_TXD: M1.D22(UART_4_TXD) ; port UART_4_TXD
USB_1_D_N: M1.A71(USB_1_D_N) ; port USB_1_D_N
USB_1_D_P: M1.A70(USB_1_D_P) ; port USB_1_D_P
USB_1_EN: M1.B77(USB_1_EN) ; port USB_1_EN
USB_1_INT#: M1.B74(USB_1_INT#) ; port USB_1_INT#
USB_1_OC#: M1.B75(USB_1_OC#) ; port USB_1_OC#
USB_1_SBU_N: M1.A67(USB_1_SBU2) ; port USB_1_SBU2
USB_1_SBU_P: M1.A68(USB_1_SBU1) ; port USB_1_SBU1
USB_1_SSRX1_N: M1.A61(USB_1_SSRX1_N) ; port USB_1_SSRX1_N
USB_1_SSRX1_P: M1.A62(USB_1_SSRX1_P) ; port USB_1_SSRX1_P
USB_1_SSRX2_N: M1.A73(USB_1_SSRX2_N) ; port USB_1_SSRX2_N
USB_1_SSRX2_P: M1.A74(USB_1_SSRX2_P) ; port USB_1_SSRX2_P
USB_1_SSTX1_N: M1.A65(USB_1_SSTX1_N) ; port USB_1_SSTX1_N
USB_1_SSTX1_P: M1.A64(USB_1_SSTX1_P) ; port USB_1_SSTX1_P
USB_1_SSTX2_N: M1.A77(USB_1_SSTX2_N) ; port USB_1_SSTX2_N
USB_1_SSTX2_P: M1.A76(USB_1_SSTX2_P) ; port USB_1_SSTX2_P
USB_1_VBUS: M1.B76(USB_1_VBUS) ; port USB_1_VBUS
USB_2_D_N: M1.A85(USB_2_D_N) ; port USB_2_D_N
USB_2_D_P: M1.A86(USB_2_D_P) ; port USB_2_D_P
USB_2_EN: M1.B80(USB_2_EN) ; port USB_2_EN
USB_2_SSRX1_N: M1.A82(USB_2_SSRX1_N) ; port USB_2_SSRX1_N
USB_2_SSRX1_P: M1.A83(USB_2_SSRX1_P) ; port USB_2_SSRX1_P
USB_2_SSTX1_N: M1.A79(USB_2_SSTX1_N) ; port USB_2_SSTX1_N
USB_2_SSTX1_P: M1.A80(USB_2_SSTX1_P) ; port USB_2_SSTX1_P
VCC_BACKUP: M1.B100(VCC_BACKUP) ; port VCC_BACKUP
NetJ94_2: J94.2 J95.1
NetJ94_3: J94.3 J95.2
NetJ94_4: J94.4 J95.3
NetJ94_5: J94.5 J95.4
NetJ94_6: J94.6 J95.5
NetJ96_2: J96.2 J97.1
NetJ96_3: J96.3 J97.2
NetJ96_4: J96.4 J97.3
NetJ96_5: J96.5 J97.4
NetJ96_6: J96.6 J97.5
NetM1_B78: M1.B78(USB_2_OC#) R66.2 R459.2
NetM1_B79: M1.B79(USB_2_VBUS) R65.2 R352.1

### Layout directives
differential pair; differential pair class CSI_1: CSI_1_CLK_N, CSI_1_CLK_P, CSI_1_D0_N, CSI_1_D0_P, CSI_1_D1_N, CSI_1_D1_P, CSI_1_D2_N, CSI_1_D2_P, CSI_1_D3_N, CSI_1_D3_P
differential pair; differential pair class DSI: DSI_1_CLK_N, DSI_1_CLK_P, DSI_1_D0_N, DSI_1_D0_P, DSI_1_D1_N, DSI_1_D1_P, DSI_1_D2_N, DSI_1_D2_P, DSI_1_D3_N, DSI_1_D3_P
differential pair; differential pair class DP: DP_1_AUX_N, DP_1_AUX_P, DP_1_LANE0_N, DP_1_LANE0_P, DP_1_LANE1_N, DP_1_LANE1_P, DP_1_LANE2_N, DP_1_LANE2_P, DP_1_LANE3_N, DP_1_LANE3_P
differential pair; differential pair class CSI_2: CSI_2_CLK_N, CSI_2_CLK_P, CSI_2_D0_N, CSI_2_D0_P, CSI_2_D1_N, CSI_2_D1_P, CSI_2_D2_N, CSI_2_D2_P, CSI_2_D3_N, CSI_2_D3_P
differential pair; differential pair class PCIe_2: PCIE_2_CLK_N, PCIE_2_CLK_P, PCIE_2_L0_RX_N, PCIE_2_L0_RX_P, PCIE_2_L0_TX_N, PCIE_2_L0_TX_P, PCIE_2_L1_RX_N, PCIE_2_L1_RX_P, PCIE_2_L1_TX_N, PCIE_2_L1_TX_P
differential pair; differential pair class PCIe_1: PCIE_1_CLK_N, PCIE_1_CLK_P, PCIE_1_L0_RX_N, PCIE_1_L0_RX_P, PCIE_1_L0_TX_N, PCIE_1_L0_TX_P, PCIE_1_L1_RX_N, PCIE_1_L1_RX_P, PCIE_1_L1_TX_N, PCIE_1_L1_TX_P
net class 50R: (no net found under the mark)
differential pair; differential pair class USB; differential pair class USB_1: USB_1_D_N, USB_1_D_P
differential pair; differential pair class USB; differential pair class USB_1_SSTX1: USB_1_SSTX1_N, USB_1_SSTX1_P
differential pair; differential pair class USB; differential pair class USB_1_SSRX1: USB_1_SSRX1_N, USB_1_SSRX1_P
differential pair; differential pair class USB; differential pair class USB_2_SSRX1: USB_2_SSRX1_N, USB_2_SSRX1_P
differential pair; differential pair class USB; differential pair class USB_2_SSTX1: USB_2_SSTX1_N, USB_2_SSTX1_P
differential pair; differential pair class ETH1: ETH_1_MDI0_N, ETH_1_MDI0_P, ETH_1_MDI1_N, ETH_1_MDI1_P, ETH_1_MDI2_N, ETH_1_MDI2_P, ETH_1_MDI3_N, ETH_1_MDI3_P
differential pair; differential pair class USB; differential pair class USB_2: USB_2_D_N, USB_2_D_P
net class QSPI: (no net found under the mark)
differential pair; differential pair class USB; differential pair class USB_1_SSTX2: USB_1_SSTX2_N, USB_1_SSTX2_P
differential pair; differential pair class USB; differential pair class USB_1_SSRX2: USB_1_SSRX2_N, USB_1_SSRX2_P
differential pair; differential pair class XGMII: ETH_2_XGMII_RX_N, ETH_2_XGMII_RX_P, ETH_2_XGMII_TX_N, ETH_2_XGMII_TX_P
differential pair; differential pair class MSP: MSP_1_RX_N, MSP_1_RX_P, MSP_1_TX_N, MSP_1_TX_P, MSP_2_RX_N, MSP_2_RX_P, MSP_2_TX_N, MSP_2_TX_P, MSP_3_RX_N, MSP_3_RX_P, MSP_3_TX_N, MSP_3_TX_P, MSP_4_RX_N, MSP_4_RX_P, MSP_4_TX_N, MSP_4_TX_P, MSP_5_RX_N, MSP_5_RX_P, MSP_5_TX_N, MSP_5_TX_P, MSP_6_RX_N, MSP_6_RX_P, MSP_6_TX_N, MSP_6_TX_P, MSP_7_RX_N, MSP_7_RX_P, MSP_7_TX_N, MSP_7_TX_P, MSP_8_RX_N, MSP_8_RX_P, MSP_8_TX_N, MSP_8_TX_P, MSP_9_RX_N, MSP_9_RX_P, MSP_9_TX_N, MSP_9_TX_P, MSP_10_RX_N, MSP_10_RX_P, MSP_10_TX_N, MSP_10_TX_P, MSP_11_RX_N, MSP_11_RX_P, MSP_11_TX_N, MSP_11_TX_P, MSP_12_RX_N, MSP_12_RX_P, MSP_12_TX_N, MSP_12_TX_P, MSP_13_RX_N, MSP_13_RX_P, MSP_13_TX_N, MSP_13_TX_P, MSP_14_RX_N, MSP_14_RX_P, MSP_14_TX_N, MSP_14_TX_P, MSP_15_RX_N, MSP_15_RX_P, MSP_15_TX_N, MSP_15_TX_P, MSP_16_RX_N, MSP_16_RX_P, MSP_16_TX_N, MSP_16_TX_P, MSP_17_RX_N, MSP_17_RX_P, MSP_17_TX_N, MSP_17_TX_P
net class SPI: (no net found under the mark)
net class SD: (no net found under the mark)

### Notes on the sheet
- SOM Connector
- @{"Id":"CBCSBYQF\WLJRWLHU","ObjectType":2} Assembly option only required for errata of V1.0A Aquila SoM
- Aquila AM69 Errata HAR-11843

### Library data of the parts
C51-C64 = 1314-Cap-0805-22uF/16V: (-55 to 85 DegC) CAP CER 22uF 16V X5R 0805; MfrNo: CL21A226MOQNNNE; Mfr: Samsung; PN: 1314; Alt: CL21A226MOCLRNC,CL21A226KOQNNNG,GRM21BR61C226ME44L,EMK212BBJ226MG-T
J94 J96 = 2189-Conn-Hdr 1x6 2.54MM F: (-40 to 125 DegC) CONN HEADER FEMALE 1x6 6POS  2.54MM TH; Mfr: Wurth Electronics; PN: 2189
J95 J97 = 2368-Conn-POGO 1x5 2.54MM: CONN SPRING PISTON 5POS PCB 2.54MM TH; Mfr: Mill-Max; PN: 2368
M1 = 2421-Conn-Toradex-Aquila: (-55 to 125 DegC) CONN AcceleRate HD APM6 0.635MM 400POS SMD HIGH DENSITY ARRAY, 5MM STACK HEIGHT (UN-BALLED); Mfr: Samtec; PN: 2421
ME5-ME12 = 2405-Post-M3-5mm: (-55 to 155 DegC) ROUND STANDOFF M3X0.5 BRASS 5MM; Mfr: Sinhoo; MfrNo: SMTSO3050CTJ; PN: 2405
R65 R66 = 0000-Res-0402-DNP: RES 0402
R352 = 1572-Res-0402-10K: (-55 to 155 DegC AEC) RES 10K OHM 1% 1/16W 100ppm 0402; Mfr: Stackpole Electronics; MfrNo: RMCF0402FT10K0; PN: 1572; Alt: AC0402FR-0710KL,AC0402FR-1310KL,CRGCQ0402F10K
R459 = 1572-Res-0402-10K: (-55 to 155 DegC AEC) RES 10K OHM 1% 1/16W 100ppm 0402; Mfr: Stackpole Electronics; MfrNo: RMCF0402FT10K0; Alt: AC0402FR-0710KL,AC0402FR-1310KL,CRGCQ0402F10K; PN: 1572

## Sheet 600_Peripherals.SchDoc: Aquila Development Board
size A3; Organization: Toradex Solutions Inc.; Address1: 6415 Northwest Drive; Address2: Mississauga, ON, L4V 1X1; Address3: Canada; SheetNumber: 29; SheetTotal: 34
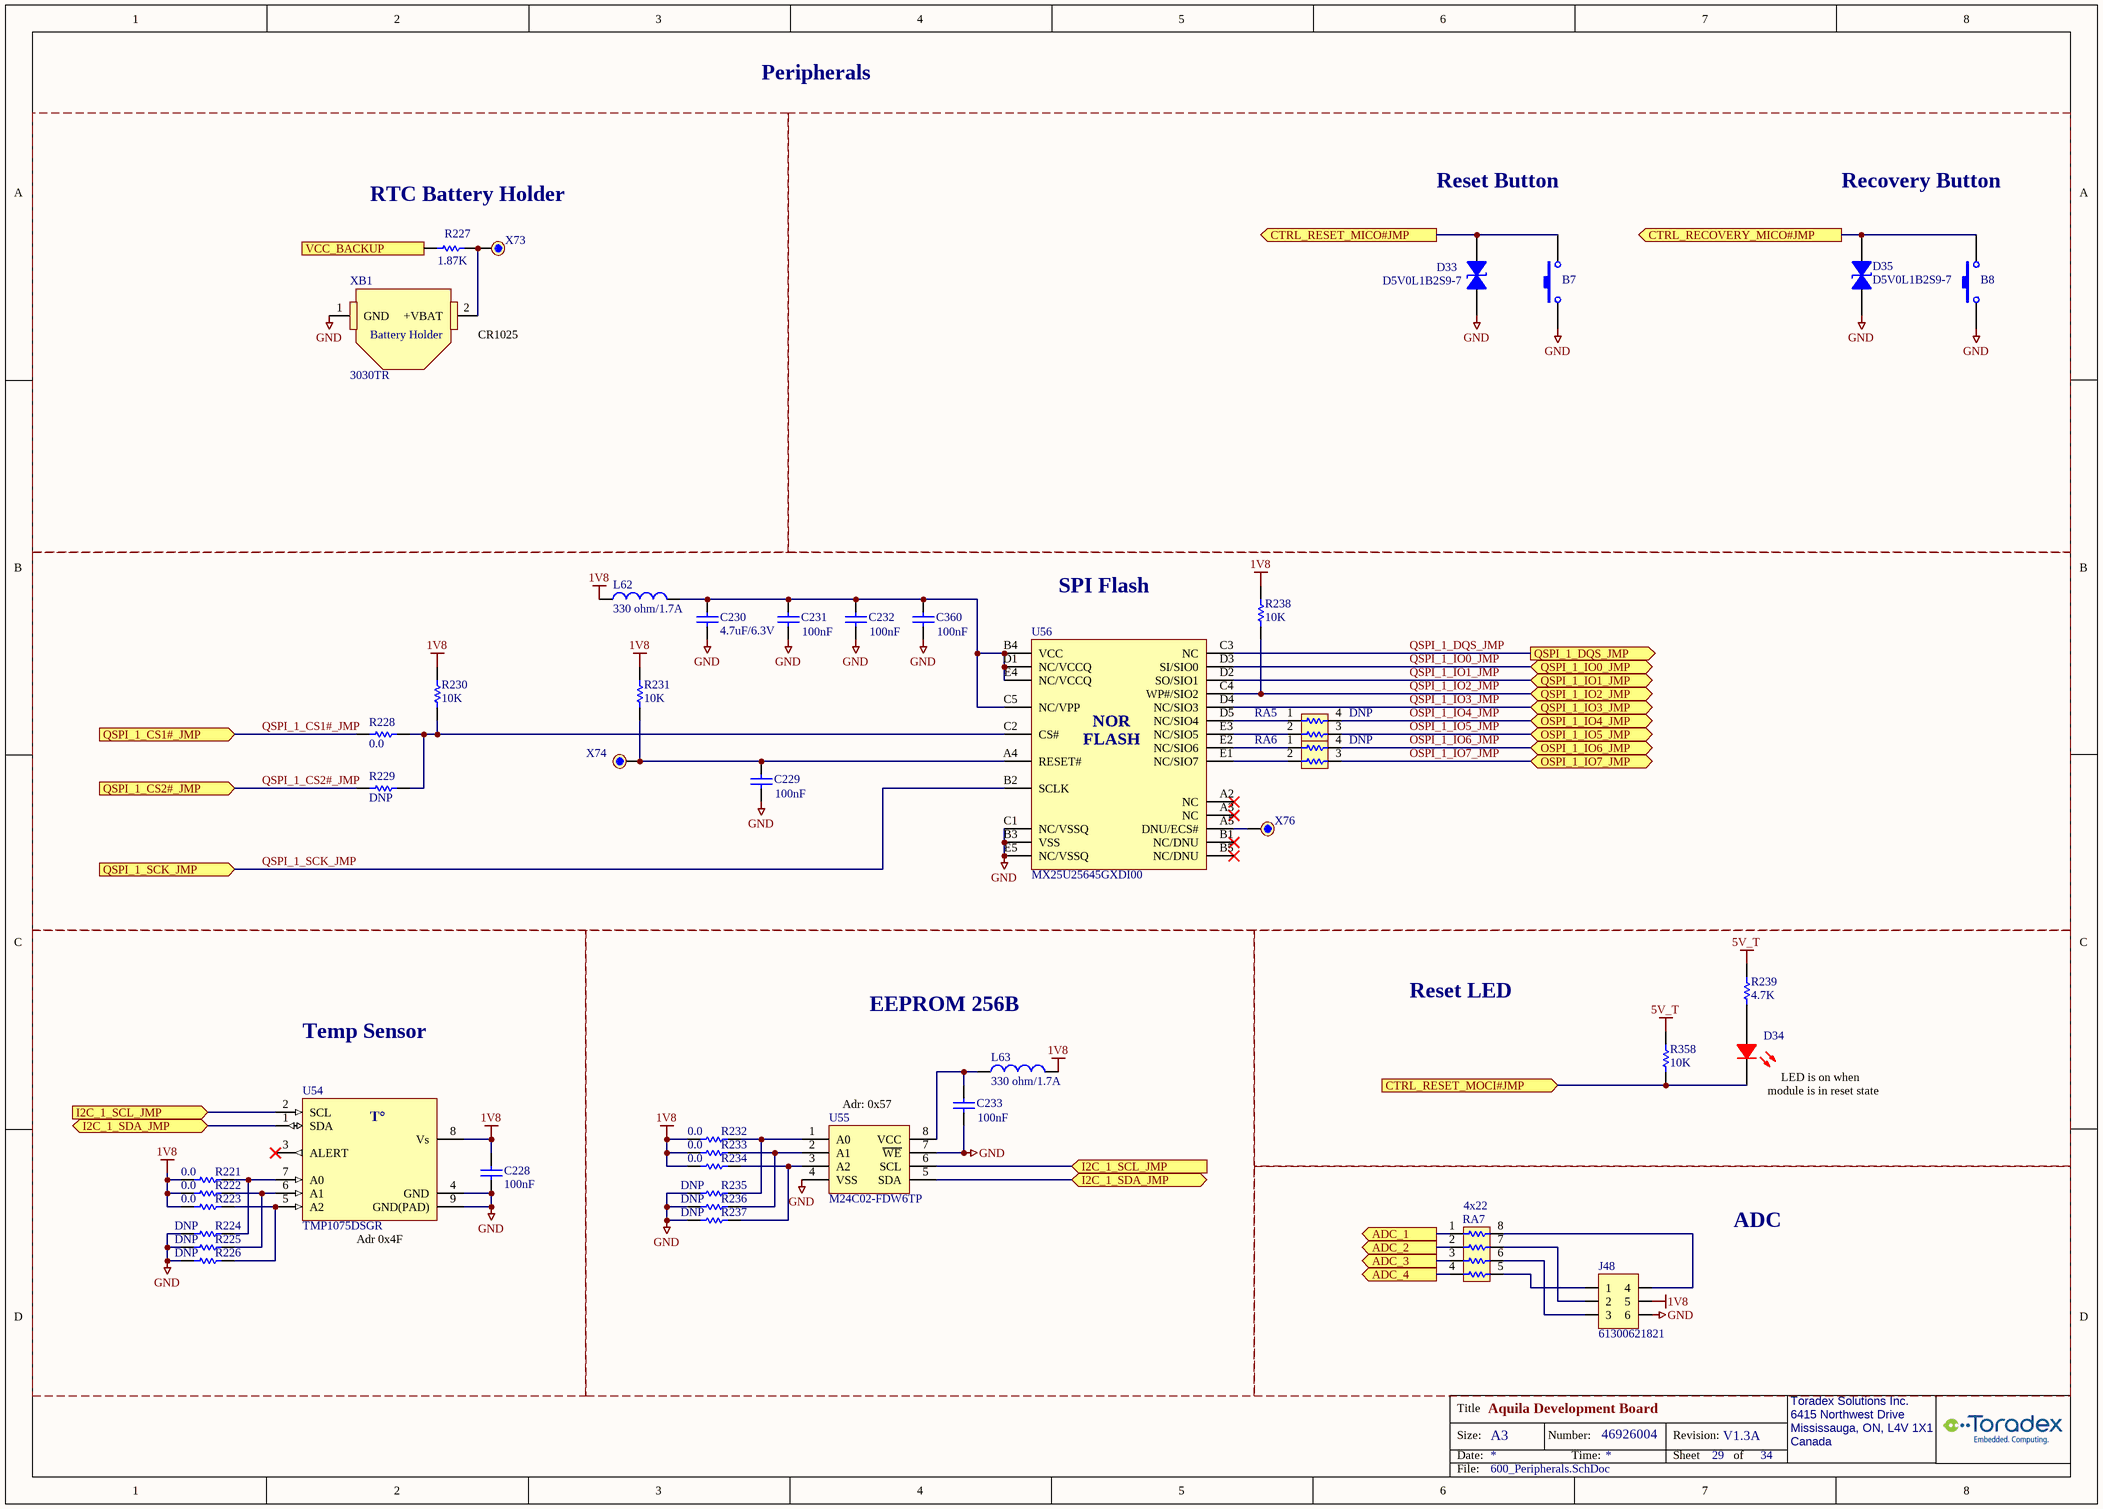
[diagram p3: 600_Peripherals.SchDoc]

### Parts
B7  B3FS-1010P  [OMRONSW_B3FS-1010P]  (value not drawn)
B8  B3FS-1010P  [OMRONSW_B3FS-1010P]  (value not drawn)
C228  100nF  [C0402_CAPC1005L]
C229  100nF  [C0402_CAPC1005L]
C230  value 4.7uF/6.3V  [C0402_CAPC1005L]  (hidden comment: 0354-Cap-0402-4.7uF/6.3V)
C231  100nF  [C0402_CAPC1005L]
C232  100nF  [C0402_CAPC1005L]
C233  100nF  [C0402_CAPC1005L]
C360  100nF  [C0402_CAPC1005L]
D33  D5V0L1B2S9-7  [SOD923_DIO]
D34  Status  [LED-SMT-0603_APT1608CGCK]  (value not drawn)
D35  D5V0L1B2S9-7  [SOD923_DIO]
J48  61300621821  [WURTH_61300621821]
L62  value 330 ohm/1.7A  [C/0603]  (hidden comment: 0405-Fer-0603-330ohm/1.7A)
L63  value 330 ohm/1.7A  [C/0603]  (hidden comment: 0405-Fer-0603-330ohm/1.7A)
R221  value 0.0  [R/0603]  (hidden comment: 0195-Res-0603-0.0ohm)
R222  value 0.0  [R/0603]  (hidden comment: 0195-Res-0603-0.0ohm)
R223  value 0.0  [R/0603]  (hidden comment: 0195-Res-0603-0.0ohm)
R224  value DNP  [R/0603]  (hidden comment: 0000-Res-0603-DNP)
R225  value DNP  [R/0603]  (hidden comment: 0000-Res-0603-DNP)
R226  value DNP  [R/0603]  (hidden comment: 0000-Res-0603-DNP)
R227  value 1.87K  [R0402_RESC1005L]  (hidden comment: 1536-Res-0402-1.87K)
R228  value 0.0  [R/0603]  (hidden comment: 0195-Res-0603-0.0ohm)
R229  value DNP  [R/0603]  (hidden comment: 0000-Res-0603-DNP)
R230  value 10K  [R0402_RESC1005L]  (hidden comment: 1572-Res-0402-10K)
R231  value 10K  [R0402_RESC1005L]  (hidden comment: 1572-Res-0402-10K)
R232  value 0.0  [R/0603]  (hidden comment: 0195-Res-0603-0.0ohm)
R233  value 0.0  [R/0603]  (hidden comment: 0195-Res-0603-0.0ohm)
R234  value 0.0  [R/0603]  (hidden comment: 0195-Res-0603-0.0ohm)
R235  value DNP  [R/0603]  (hidden comment: 0000-Res-0603-DNP)
R236  value DNP  [R/0603]  (hidden comment: 0000-Res-0603-DNP)
R237  value DNP  [R/0603]  (hidden comment: 0000-Res-0603-DNP)
R238  value 10K  [R0402_RESC1005L]  (hidden comment: 1572-Res-0402-10K)
R239  value 4.7K  [R0402_RESC1005L]  (hidden comment: 2233-Res-0402-4.7K)
R358  value 10K  [R0402_RESC1005L]  (hidden comment: 1572-Res-0402-10K)
RA5  value DNP  [EXB34V]  (hidden comment: 0000-ResArr-0606-DNP)
RA6  value DNP  [EXB34V]  (hidden comment: 0000-ResArr-0606-DNP)
RA7  value 4x22  [RES_4_x_0804]  (hidden comment: 1848-ResArr-0804-22ohm)
U54  TMP1075DSGR  [WSON-8(2.1x2.1)_PAD]
U55  M24C02-FDW6TP  [TSSOP8]
U56  MX25U25645GXDI00  [T-PBGA-24]
X73  000-TestPoint  [TestPoint_1]  (value not drawn)
X74  000-TestPoint  [TestPoint_1]  (value not drawn)
X76  000-TestPoint  [TestPoint_1]  (value not drawn)
XB1  3030TR  [T_Keystone_3030]

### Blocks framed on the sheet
RTC Battery Holder: R227 X73 XB1
SPI Flash: C229-C232 C360 L62 R228-R231 R238 RA5 RA6 U56 X74 X76
Temp Sensor: C228 R221-R226 U54
EEPROM 256B: C233 L63 R232-R237 U55
Reset LED: D34 R239 R358
ADC: J48 RA7

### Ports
ADC_1 (out), ADC_2 (out), ADC_3 (out), ADC_4 (out), CTRL_RECOVERY_MICO#JMP (out), CTRL_RESET_MICO#JMP (out), CTRL_RESET_MOCI#JMP (in), I2C_1_SCL_JMP (in), I2C_1_SDA_JMP (bidir), OSPI_1_IO4_JMP (bidir), OSPI_1_IO5_JMP (bidir), OSPI_1_IO6_JMP (bidir), OSPI_1_IO7_JMP (bidir), QSPI_1_CS1#_JMP (in), QSPI_1_CS2#_JMP (in), QSPI_1_DQS_JMP (out), QSPI_1_IO0_JMP (bidir), QSPI_1_IO1_JMP (bidir), QSPI_1_IO2_JMP (bidir), QSPI_1_IO3_JMP (bidir), QSPI_1_SCK_JMP (in), VCC_BACKUP (out)

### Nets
1V8: C228.2 J48.5 L62.2 L63.1 R221.1 R222.1 R223.1 R230.1 R231.1 R232.1 R233.1 R234.1 R238.1 U54.8(Vs)
5V_T: R239.1 R358.1
GND: B7.1 B8.1 C228.1 C229.1 C230.1 C231.1 C232.1 C233.1 C360.1 D33.2 D35.2 J48.6 R224.1 R225.1 R226.1 R235.1 R236.1 R237.1 U54.4(GND) U54.9(GND(PAD)) U55.4(VSS) U55.7(~{WE}) U56.B3(VSS) U56.C1(NC/VSSQ) U56.E5(NC/VSSQ) XB1.1(GND)
ADC_1: RA7.1 ; port ADC_1
ADC_2: RA7.2 ; port ADC_2
ADC_3: RA7.3 ; port ADC_3
ADC_4: RA7.4 ; port ADC_4
CTRL_RECOVERY_MICO#JMP: B8.3 D35.1 ; port CTRL_RECOVERY_MICO#JMP
CTRL_RESET_MICO#JMP: B7.3 D33.1 ; port CTRL_RESET_MICO#JMP
CTRL_RESET_MOCI#JMP: D34.2(K) R358.2 ; port CTRL_RESET_MOCI#JMP
I2C_1_SCL_JMP: U54.2(SCL) U55.6(SCL) ; port I2C_1_SCL_JMP
I2C_1_SDA_JMP: U54.1(SDA) U55.5(SDA) ; port I2C_1_SDA_JMP
OSPI_1_IO4_JMP: RA5.4 ; port OSPI_1_IO4_JMP
OSPI_1_IO5_JMP: RA5.3 ; port OSPI_1_IO5_JMP
OSPI_1_IO6_JMP: RA6.4 ; port OSPI_1_IO6_JMP
OSPI_1_IO7_JMP: RA6.3 ; port OSPI_1_IO7_JMP
QSPI_1_CS1#_JMP: R228.2 ; port QSPI_1_CS1#_JMP
QSPI_1_CS2#_JMP: R229.2 ; port QSPI_1_CS2#_JMP
QSPI_1_DQS_JMP: U56.C3(NC) ; port QSPI_1_DQS_JMP
QSPI_1_IO0_JMP: U56.D3(SI/SIO0) ; port QSPI_1_IO0_JMP
QSPI_1_IO1_JMP: U56.D2(SO/SIO1) ; port QSPI_1_IO1_JMP
QSPI_1_IO2_JMP: R238.2 U56.C4(WP#/SIO2) ; port QSPI_1_IO2_JMP
QSPI_1_IO3_JMP: U56.D4(NC/SIO3) ; port QSPI_1_IO3_JMP
QSPI_1_SCK_JMP: U56.B2(SCLK) ; port QSPI_1_SCK_JMP
VCC_BACKUP: R227.2 ; port VCC_BACKUP
NetC229_2: C229.2 R231.2 U56.A4(RESET#) X74.1
NetC230_2: C230.2 C231.2 C232.2 C360.2 L62.1 U56.B4(VCC) U56.C5(NC/VPP) U56.D1(NC/VCCQ) U56.E4(NC/VCCQ)
NetC233_2: C233.2 L63.2 U55.8(VCC)
NetD34_1: D34.1(A) R239.2
NetJ48_1: J48.1 RA7.5
NetJ48_2: J48.2 RA7.7
NetJ48_3: J48.3 RA7.6
NetJ48_4: J48.4 RA7.8
NetR221_2: R221.2 R224.2 U54.7(A0)
NetR222_2: R222.2 R225.2 U54.6(A1)
NetR223_2: R223.2 R226.2 U54.5(A2)
NetR227_1: R227.1 X73.1 XB1.2(+VBAT)
NetR228_1: R228.1 R229.1 R230.2 U56.C2(CS#)
NetR232_2: R232.2 R235.2 U55.1(A0)
NetR233_2: R233.2 R236.2 U55.2(A1)
NetR234_2: R234.2 R237.2 U55.3(A2)
NetRA5_1: RA5.1 U56.D5(NC/SIO4)
NetRA5_2: RA5.2 U56.E3(NC/SIO5)
NetRA6_1: RA6.1 U56.E2(NC/SIO6)
NetRA6_2: RA6.2 U56.E1(NC/SIO7)
NetU56_A5: U56.A5(DNU/ECS#) X76.1

Not connected (* = marked no-connect by the designer): U54 3(ALERT)*; U56 A2(NC)* A3(NC)* B1(NC/DNU)* B5(NC/DNU)*

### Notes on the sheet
- Peripherals
- Reset Button
- Recovery Button
- (near XB1) CR1025
- (near U55) Adr: 0x57
- (near D34) module is in reset state
- (near D34) LED is on when
- (near U54) Adr 0x4F

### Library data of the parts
B7 B8 = 1511-Push Button: (-25 to 70 DegC) SWITCH TACTILE SPST-NO 0.05A 24V H:4.3mm Switch-PushButton; Mfr: Omron; PN: 1511; Alt: in bag: B3FS-1010; Note: similar to PN243 but taller
C228 C229 C231-C233 C360 = 1566-Cap-0402-100nF/50V: (-55 to 125 DegC AEC) Cap Ceramic 0.1uF 50V X7R 10% 0402; MfrNo: GRT155R71H104KE01D; Mfr: Murata; Alt: CL05B104KB54PNC,GCM155R71H104ME02D,GCM155R71H104KE02D,GCM155R71H104KE02J; PN: 1566
C230 = 0354-Cap-0402-4.7uF/6.3V: (-55 to 85 DegC) CAP CER 4.7UF 6.3V 20% X5R 0402; Mfr: Murata Electronics North America; MfrNo: GRM155R60J475ME87D; Alt: 1276-1483-1-ND; Alt2: 490-5915-1-ND; PN: 354
D33 D35 = 1655-D5V0L1B2S9-7: (-65 to 155 DegC) TVS DIODE Vwm:5V Vcl:14V@6A SOD-923; Mfr: Diodes; PN: 1655
D34 = 1859-LED Red 0603: (-30 to 85 DegC) LED RED 0603 99mcd Vf:2.0V; Mfr: Vishay Lite-On; MfrNo: LTST-C190KRKT; Alt: PN331; PN: 1859
J48 = 2193-Conn-Hdr 2x3 2.54MM F: (-40 to 125 DegC) CONN HEADER FEMALE 2x3 6POS 2.54MM TH; Mfr: Wurth Electronics; PN: 2193
L62 L63 = 0405-Fer-0603-330ohm/1.7A: (-55 to 125 DegC) FERRITE BEAD 330 OHM 0603 1.7A 80mohm, typ 48mohm; Mfr: TDK Corporation; MfrNo: MPZ1608S331ATA00; PN: 405; TR: 445-5221-2-ND; DR: 445-5221-6-ND; DR2: 810-MPZ1608S331ATA00
R221-R223 R228 R232-R234 = 0195-Res-0603-0.0ohm: (-55 to 155 DegC) RES 0.0 OHM 1/10W JUMP 0603; Mfr: Samsung; MfrNo: RC1608J000CS; Alt: 311-0.0GRCT-ND; Alt2: A106051CT-ND; PN: 195; TR: 1276-3510-2-ND
R224-R226 R229 R235-R237 = 0000-Res-0603-DNP: RES 0603
R227 = 1536-Res-0402-1.87K: (-55 to 155 DegC AEC) RES 1.87K OHM 1% 1/16W 100ppm 0402; MfrNo: RMCF0402FT1K87; Mfr: Stackpole Electronics; Alt: AC0402FR-071K87L,RK73H1ETTP1871F,ERJ-2RKF1871X; PN: 1536
R230 R231 R238 R358 = 1572-Res-0402-10K: as R459 on sheet 200_Aquila
R239 = 2233-Res-0402-4.7K: (-55 to 155 DegC) RES 4.70K OHM 1/16W 1% 0402 100ppm; MfrNo: RC0402FR-074K7L; Mfr: Yageo; PN: 2233
RA5 RA6 = 0000-ResArr-0606-DNP: RES ARRAY 2 RES 0606
RA7 = 1848-ResArr-0804-22ohm: (-55 to 125 DegC) RES ARRAY 4 RES 22 OHM 0804 +/-300ppm SMD; MfrNo: CAT10A-220J4LF; Mfr: Bourns; PN: 1848; Alt: PN1819
U54 = 1853-TMP1075DSGR: (-55 to 125 DegC) IC Temp Sensor I2C 1.7-5.5V WSON8; Mfr: Texas Instruments; PN: 1853
U55 = 0905-M24C02: (-40 to 85 DegC) IC EEPROM 2KBIT (256B) 400KHZ 8TSSOP 1.7-5.5V adr 0x50; Mfr: STMicroelectronics; PN: 905; Alt: M24C02-WDW6TP,M24C02-DRDW8TP/K, M24C02-DRDW3TP/K , M24C02-RDW6TP
U56 = 2211-MX25U25645GXDI00: (-40 to 85 DegC) IC FLASH 256MBIT SPI/QU 1.65-2V 24TBGA; Mfr: Macronix; PN: 2211
X73 X74 X76 = 000-TestPoint: TestPoint TH; Note: this is PCB footprint only, no parts to buy or assemble
XB1 = 1664-Conn-BatHolder: Battery Holder Coin 10mm SMD; Mfr: Keystone Electronics; PN: 1664

## Sheet 100_Power_1.SchDoc: Aquila Development Board
size Letter; Organization: Linear Computing Inc.; Address1: 6415 Northwest Drive; Address2: Mississauga, ON, L4V1X1; Address3: Canada; SheetNumber: 3; SheetTotal: 34
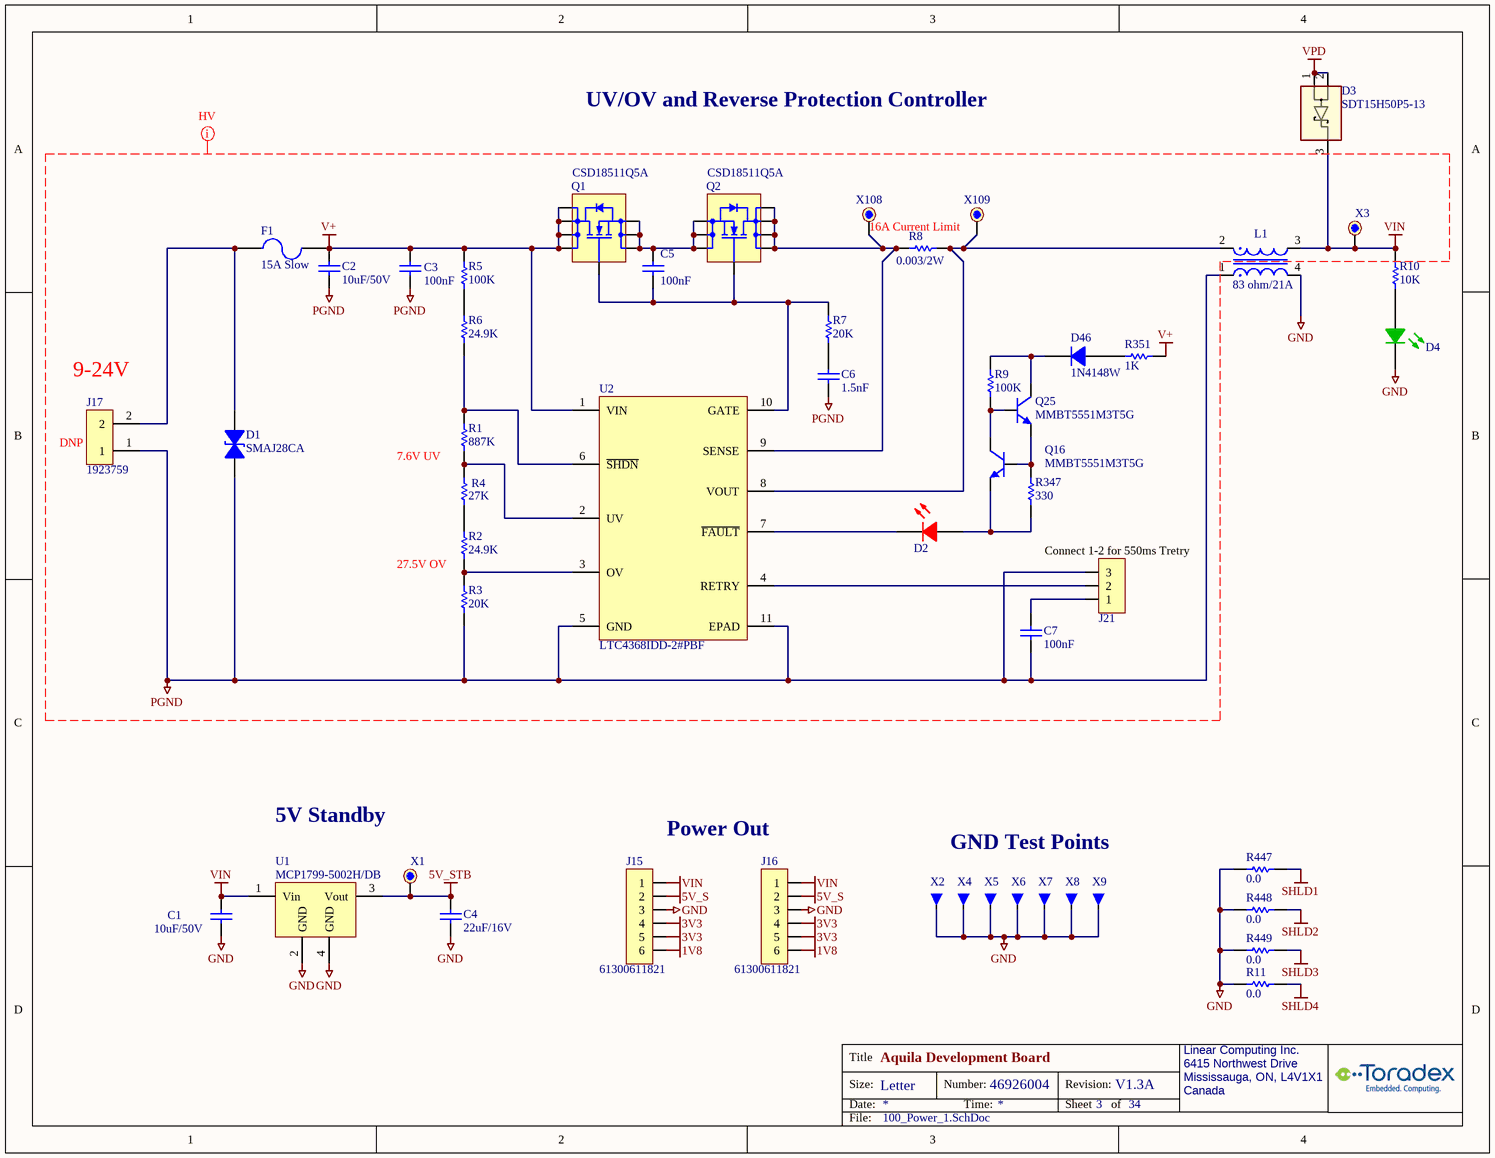
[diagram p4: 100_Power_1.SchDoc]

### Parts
C1  10uF/50V  [CAPC3225N]
C2  10uF/50V  [CAPC3225N]
C3  100nF  [C0402_CAPC1005L]
C4  value 22uF/16V  [C/0805]  (hidden comment: 1314-Cap-0805-22uF/16V)
C5  100nF  [C0402_CAPC1005L]
C6  value 1.5nF  [C0402_CAPC1005L]  (hidden comment: 1573-Cap-0402-1.5nF)
C7  100nF  [C0402_CAPC1005L]
D1  SMAJ28CA  [SMAJ_TRANSIL]
D2  Status  [LED-SMT-0603_APT1608CGCK]  (value not drawn)
D3  SDT15H50P5-13  [POWERDI-5_DIO]
D4  Status  [LED-SMT-0603_APT1608CGCK]  (value not drawn)
D46  1N4148W  [SOD123_ALT]
F1  15A Slow  [FUSE_1206_(3216)]
J15  61300611821  [WURTH_61300611821]
J16  61300611821  [WURTH_61300611821]
J17  1923759  [PHOENIX_1923759]  (no BOM)
J21  68001-203HLF  [CON_HDR1X3]  (value not drawn)
L1  83 ohm/21A  [WE-CMS_9085]
Q1  CSD18511Q5A  [VSONP-8 (5x6)]
Q2  CSD18511Q5A  [VSONP-8 (5x6)]
Q16  MMBT5551M3T5G  [SOT-723_0P85X1P25_ONS]
Q25  MMBT5551M3T5G  [SOT-723_0P85X1P25_ONS]
R1  value 887K  [R0402_RESC1005L]  (hidden comment: 1809-Res-0402-887K)
R2  value 24.9K  [R/0603]  (hidden comment: 1144-Res-0603-24.9K)
R3  value 20K  [R/0603]  (hidden comment: 1216-Res-0603-20K)
R4  value 27K  [R0402_RESC1005L]  (hidden comment: 1538-Res-0402-27k)
R5  value 100K  [R0402_RESC1005L]  (hidden comment: 1977-Res-0402-100K)
R6  value 24.9K  [R/0603]  (hidden comment: 1144-Res-0603-24.9K)
R7  value 20K  [R/0603]  (hidden comment: 1216-Res-0603-20K)
R8  value 0.003/2W  [R/2512]  (hidden comment: 2225-Res-2512-0.003ohm-2W)
R9  value 100K  [R0402_RESC1005L]  (hidden comment: 1977-Res-0402-100K)
R10  value 10K  [R0402_RESC1005L]  (hidden comment: 1572-Res-0402-10K)
R11  value 0.0  [R/0603]  (hidden comment: 0195-Res-0603-0.0ohm)
R347  value 330  [R0402_RESC1005L]  (hidden comment: 1807-Res-0402-330Ohm)
R351  value 1K  [R0402_RESC1005L]  (hidden comment: 1650-Res-0402-1K)
R447  value 0.0  [R/0603]  (hidden comment: 0195-Res-0603-0.0ohm)
R448  value 0.0  [R/0603]  (hidden comment: 0195-Res-0603-0.0ohm)
R449  value 0.0  [R/0603]  (hidden comment: 0195-Res-0603-0.0ohm)
U1  MCP1799-5002H/DB  [SOT223]
U2  LTC4368IDD-2#PBF  [10-DFN (3x3)_ADI]
X1  000-TestPoint  [TestPoint_1]  (value not drawn)
X2  5011  [TestPoint_4]  (value not drawn)
X3  000-TestPoint  [TestPoint_1]  (value not drawn)
X4  5011  [TestPoint_4]  (value not drawn)
X5  5011  [TestPoint_4]  (value not drawn)
X6  5011  [TestPoint_4]  (value not drawn)
X7  5011  [TestPoint_4]  (value not drawn)
X8  5011  [TestPoint_4]  (value not drawn)
X9  5011  [TestPoint_4]  (value not drawn)
X108  000-TestPoint  [TestPoint_1]  (value not drawn)
X109  000-TestPoint  [TestPoint_1]  (value not drawn)

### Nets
1V8: J15.6 J16.6
3V3: J15.4 J15.5 J16.4 J16.5
5V_S: J15.2 J16.2
5V_STB: C4.2 U1.3(Vout) X1.1
GND: C1.1 C4.1 D4.2(K) J15.3 J16.3 L1.4 R11.2 R447.2 R448.2 R449.2 U1.2(GND) U1.4(GND) X2.1 X4.1 X5.1 X6.1 X7.1 X8.1 X9.1
PGND: C2.1 C3.2 C6.1 C7.2 D1.1 J17.1 J21.3 L1.1 R3.1 U2.5(GND) U2.11(EPAD)
SHLD1: R447.1
SHLD2: R448.1
SHLD3: R449.1
SHLD4: R11.1
V+: C2.2 C3.1 F1.2 Q1.5(D) Q1.6(D) Q1.7(D) Q1.8(D) R5.2 R351.2 U2.1(VIN)
VIN: C1.2 D3.3 J15.1 J16.1 L1.3 R10.1 U1.1(Vin) X3.1
VPD: D3.1 D3.2
NetC5_1: C5.1 Q1.4(G) Q2.4(G) R7.2 U2.10(GATE)
NetC5_2: C5.2 Q1.1(S) Q1.2(S) Q1.3(S) Q2.1(S) Q2.2(S) Q2.3(S)
NetC6_2: C6.2 R7.1
NetC7_1: C7.1 J21.1
NetD1_2: D1.2 F1.1 J17.2
NetD2_1: D2.1(A) Q16.2(E) R347.2
NetD2_2: D2.2(K) U2.7(~{FAULT})
NetD4_1: D4.1(A) R10.2
NetD46_1: D46.1(A) R351.1
NetD46_3: D46.3(K) Q25.3(C) R9.2
NetJ21_2: J21.2 U2.4(RETRY)
NetL1_2: L1.2 R8.1 U2.8(VOUT) X109.1
NetQ2_5: Q2.5(D) Q2.6(D) Q2.7(D) Q2.8(D) R8.2 U2.9(SENSE) X108.1
NetQ16_1: Q16.1(B) Q25.2(E) R347.1
NetQ16_3: Q16.3(C) Q25.1(B) R9.1
NetR1_1: R1.1 R4.1 U2.2(UV)
NetR1_2: R1.2 R6.1 U2.6(~{SHDN})
NetR2_1: R2.1 R3.2 U2.3(OV)
NetR2_2: R2.2 R4.2
NetR5_1: R5.1 R6.2

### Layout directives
net class HV: GND, PGND, V+, VIN

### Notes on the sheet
- UV/OV and Reverse Protection Controller
- (near X108) 16A Current Limit
- (near J17) 9-24V
- (near J17) DNP
- 7.6V UV
- 27.5V OV
- (near J21) Connect 1-2 for 550ms Tretry
- 5V Standby
- Power Out
- GND Test Points

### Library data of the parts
C1 C2 = 1607-Cap-1206-10uF/50V: (-55 to 85 DegC) CAP CER 10UF 50V 10% X5R 1206; Mfr: Samsung; MfrNo: CL31A106KBHNNNE; Alt: CL31A106MBHNNNE,UMK316BBJ106ML-T,UMK316BBJ106KL-T,GRT31CR61H106ME01L,MSASU31LBB5106MTNA01; PN: 1607
C3 C5 C7 = 1566-Cap-0402-100nF/50V: as C228 on sheet 600_Peripherals
C4 = 1314-Cap-0805-22uF/16V: as C51 on sheet 200_Aquila
C6 = 1573-Cap-0402-1.5nF: (-55 to 125 DegC AEC) CAP CER 1.5nF 10% 50V X7R 0402; Mfr: Taiyo Yuden; MfrNo: UMK105B7152KVHF; Alt: UMK105BJ152KVHF,CL05B152KB5VPNC,GCM155R71H152KA37D; PN: 1573
D1 = 0434-SMAJ28CA: (-55 to 150 DegC) TVS DIODE 28VWM 59VC SMA; Mfr: STMicroelectronics; MfrNo: SMAJ28CA-TR; PN: 434; Alt: SMAJ28CABCT-ND; Alt2: SMAJ28CA-TPMSCT-ND
D2 = 1859-LED Red 0603: as D34 on sheet 600_Peripherals
D3 = 2201-SDT15H50P5-13: (-55 to 150 DegC) DIODE SCHOTTKY 15A 50V Vf:0.3V@1.5A 0.47V@15A SMA; Mfr: Diodes; PN: 2201
D4 = 0333-LED Green 0603: (-40 to 85 DegC) LED GREEN 0603 50mcd; MfrNo: APT1608CGCK; Mfr: Kingbright; Alt: 754-1357-1-ND; Alt2: 160-1834-1-ND; PN: 333; DR: 754-1116-6-ND; DR2: 604-APT1608CGCK
D46 = 1159-1N4148W: (-55 to 150 DegC) DIODE GEN PURP 100V 300MA SOD123; MfrNo: 1N4148W-7-F; Mfr: Diodes; PN: 1159; Alt: 1N4148WQ-7-F
F1 = 2200-Fuse 15A 1206 Slow: (-55 to 90 DegC) FUSE BOARD MOUNT 15A 63VDC SLOW; Mfr: Schurter; MfrNo: 3413.0330.22; PN: 2200; Value: 15A/63VDC
J15 J16 = 2189-Conn-Hdr 1x6 2.54MM F: as J94 on sheet 200_Aquila
J17 = 1610-Conn 2-POS R/A: (-40 to 100 DegC) TERM BLOCK HDR 2POS R/A 90DEG TH 5MM 300V/16A; Mfr: Phoenix Contact; PN: 1610; Alt: OSTOQ027151
J21 = 2539-Conn-Hdr-1x3 TH Vert: (-65 to 125 DegC) CONN HDR VERT 3x1 3pos 2.54mm 0.1in Gold no-shroud; Mfr: Amphenol ICC / FCI; PN: 2539
L1 = 2226-Ind-9x8.5-83ohm/21A-Choke: (-40 to 125 DegC AEC) CMC Choke 21A 83OHM 9x8.5x4.8mm DCR = 3mohm; Mfr: Wurth Electronics; MfrNo: 7427523; PN: 2226
Q1 Q2 = 2195-CSD18511Q5A: (-55 to 150 DegC) MOSFET N-CH 40V 27A Vth:1.8V Ron typ:3.5mohm@4.5V Vgsm:2.45V 8-VSONP (5x6); Mfr: Texas Instruments; MfrNo: CSD18511Q5AT; PN: 2195
Q16 Q25 = 1857-MMBT5551M3T5G: (-55 to 150 DegC) TRANS NPN 160V 60mA 1.2x1.2 SOT723; Mfr: ON Semiconductor; PN: 1857
R1 = 1809-Res-0402-887K: (-55 to 155 DegC AEC) RES 887K OHM 1% 1/16W 100ppm 0402; Mfr: Stackpole Electronics; MfrNo: RMCF0402FT887K; PN: 1809
R2 R6 = 1144-Res-0603-24.9K: (-55 to 155 DegC) RES SMD 24.9K OHM 1% 1/10W 0603 100ppm; MfrNo: RMCF0603FT24K9; Mfr: Stackpole Electronics; Alt: CR0603-FX-2492ELF,RC0603FR-0724K9L; PN: 1144
R3 R7 = 1216-Res-0603-20K: (-55 to 155 DegC) RES SMD 20K 1% 1/10W 0603 100ppm; Mfr: Bourns; MfrNo: CR0603-FX-2002ELF; Alt: RMCF0603FT20K0,CR0603-FX-2002ELF,RK73H1JTTD2002F,RC0603FR-0720KL; PN: 1216
R4 = 1538-Res-0402-27k: (-55 to 155 DegC AEC) RES 27K OHM 1% 1/16W 100ppm 0402; Mfr: Stackpole Electronics; MfrNo: RMCF0402FT27K0; PN: 1538; Alt: AC0402FR-0727KL,CRGCQ0402F27K
R5 R9 = 1977-Res-0402-100K: (-55 to 155 DegC) RES 100K OHM 1/16W 1% 0402 SMD; Mfr: Yageo; MfrNo: RC0402FR-07100KL; PN: 1977
R8 = 2225-Res-2512-0.003ohm-2W: (-55 to 170 DegC AEC) RES 0.003 OHM 1% 2W 2512 50ppm; Mfr: Bourns; MfrNo: CRF2512-FZ-R003ELF; PN: 2225
R10 = 1572-Res-0402-10K: as R459 on sheet 200_Aquila
R11 R447-R449 = 0195-Res-0603-0.0ohm: as R221 on sheet 600_Peripherals
R347 = 1807-Res-0402-330Ohm: (-55 to 155 DegC AEC) RES 330 OHM 1% 1/16W 100ppm 0402; Mfr: Stackpole Electronics; MfrNo: RMCF0402FT330R; PN: 1807
R351 = 1650-Res-0402-1K: (-55 to 155 DegC AEC) RES 1K OHM 1% 1/16W 100ppm 0402; MfrNo: CRGCQ0402F1K0; Mfr: TE Connectivity; Alt: CR0402AFX-1001GLF,AC0402FR-131KL,AC0402FR-071KL; PN: 1650
U1 = 1666-MCP1799: (-40 to 150 DegC) IC REG LINEAR LDO Vin: 45Vmax Vout:5V fixed 80mA SOT223-3; Mfr: Microchip; MfrNo: MCP1799T-5002H/DB; PN: 1666; Note: same component in tubes: MCP1799-5002H/DB
U2 = 2224-LTC4368IDD-2#PBF: (-40 to 85 DegC AEC) IC SURGE SUPPRESSION ADJ 2.5-60V OVERVOLTAGE/UNDERVOLTAGE/OVERCURRENT PROTECT 10DFN; Mfr: Analog Devices / Linear Technology; PN: 2224
X1 X3 X108 X109 = 000-TestPoint: as X73 on sheet 600_Peripherals
X2 X4 X5 = 1468-TestPoint3: (-40 to 85 DegC) Test Point Hook Black TH; Mfr: Keystone Electronics; MfrNo: 5281; Note: white: 5282; PN: 1468
X6-X9 = 1468-TestPoint3: (-40 to 85 DegC) Test Point Hook Black TH; Mfr: Keystone Electronics; MfrNo: 5281; PN: 1468; Note: white: 5282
